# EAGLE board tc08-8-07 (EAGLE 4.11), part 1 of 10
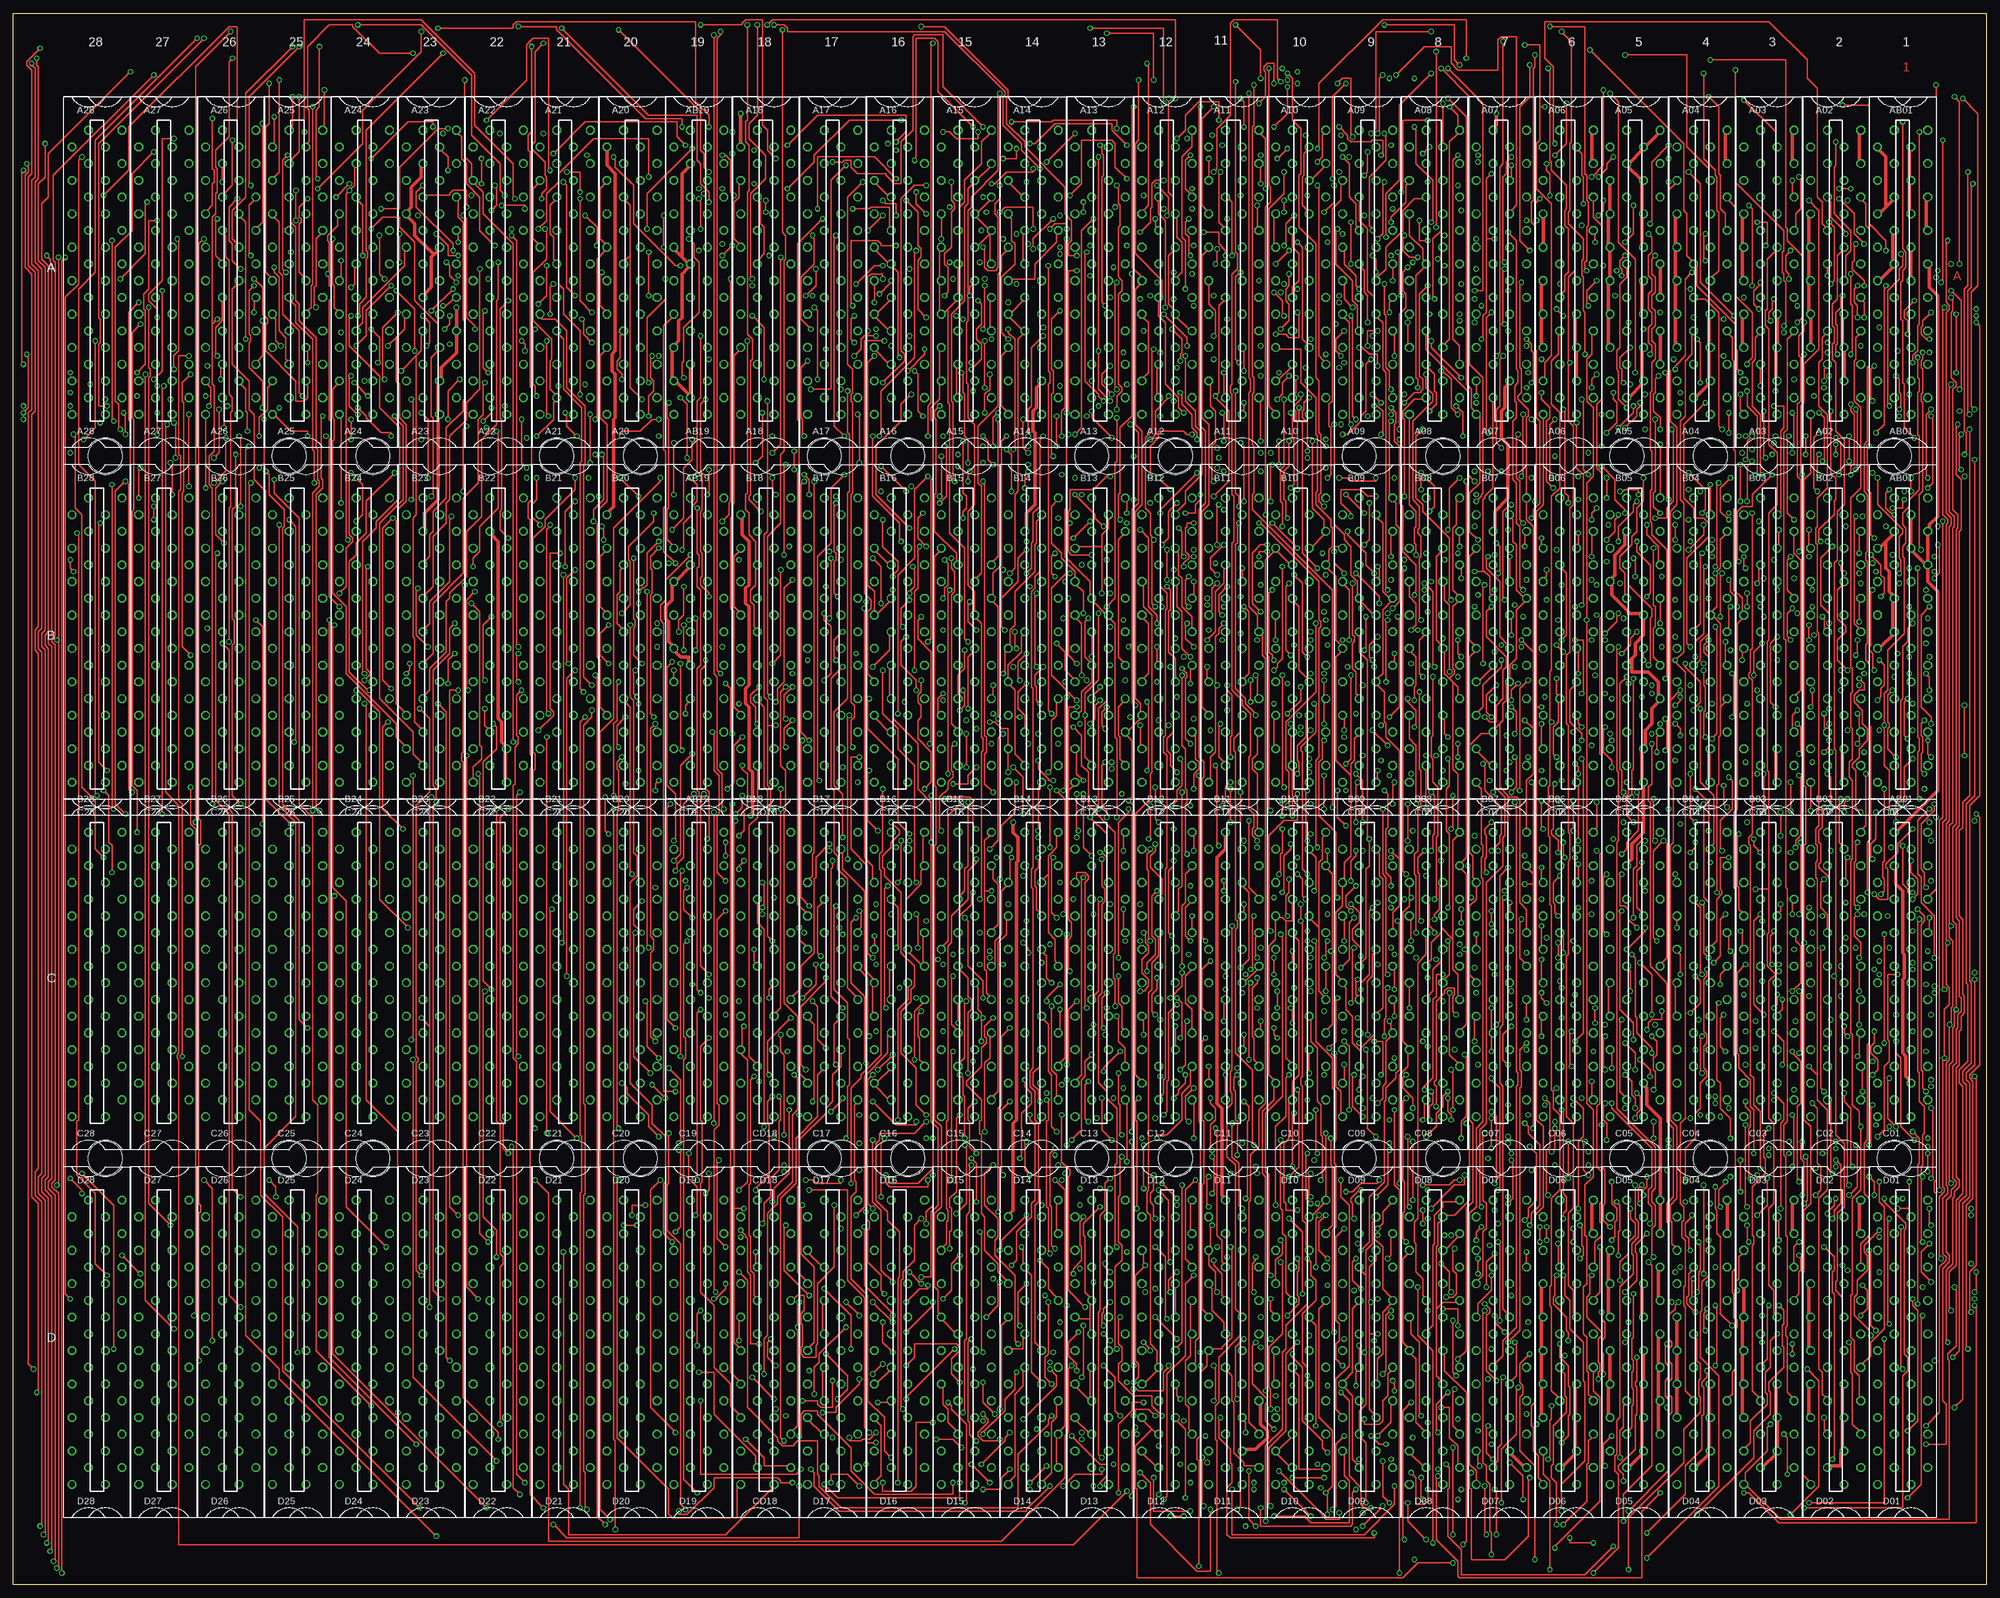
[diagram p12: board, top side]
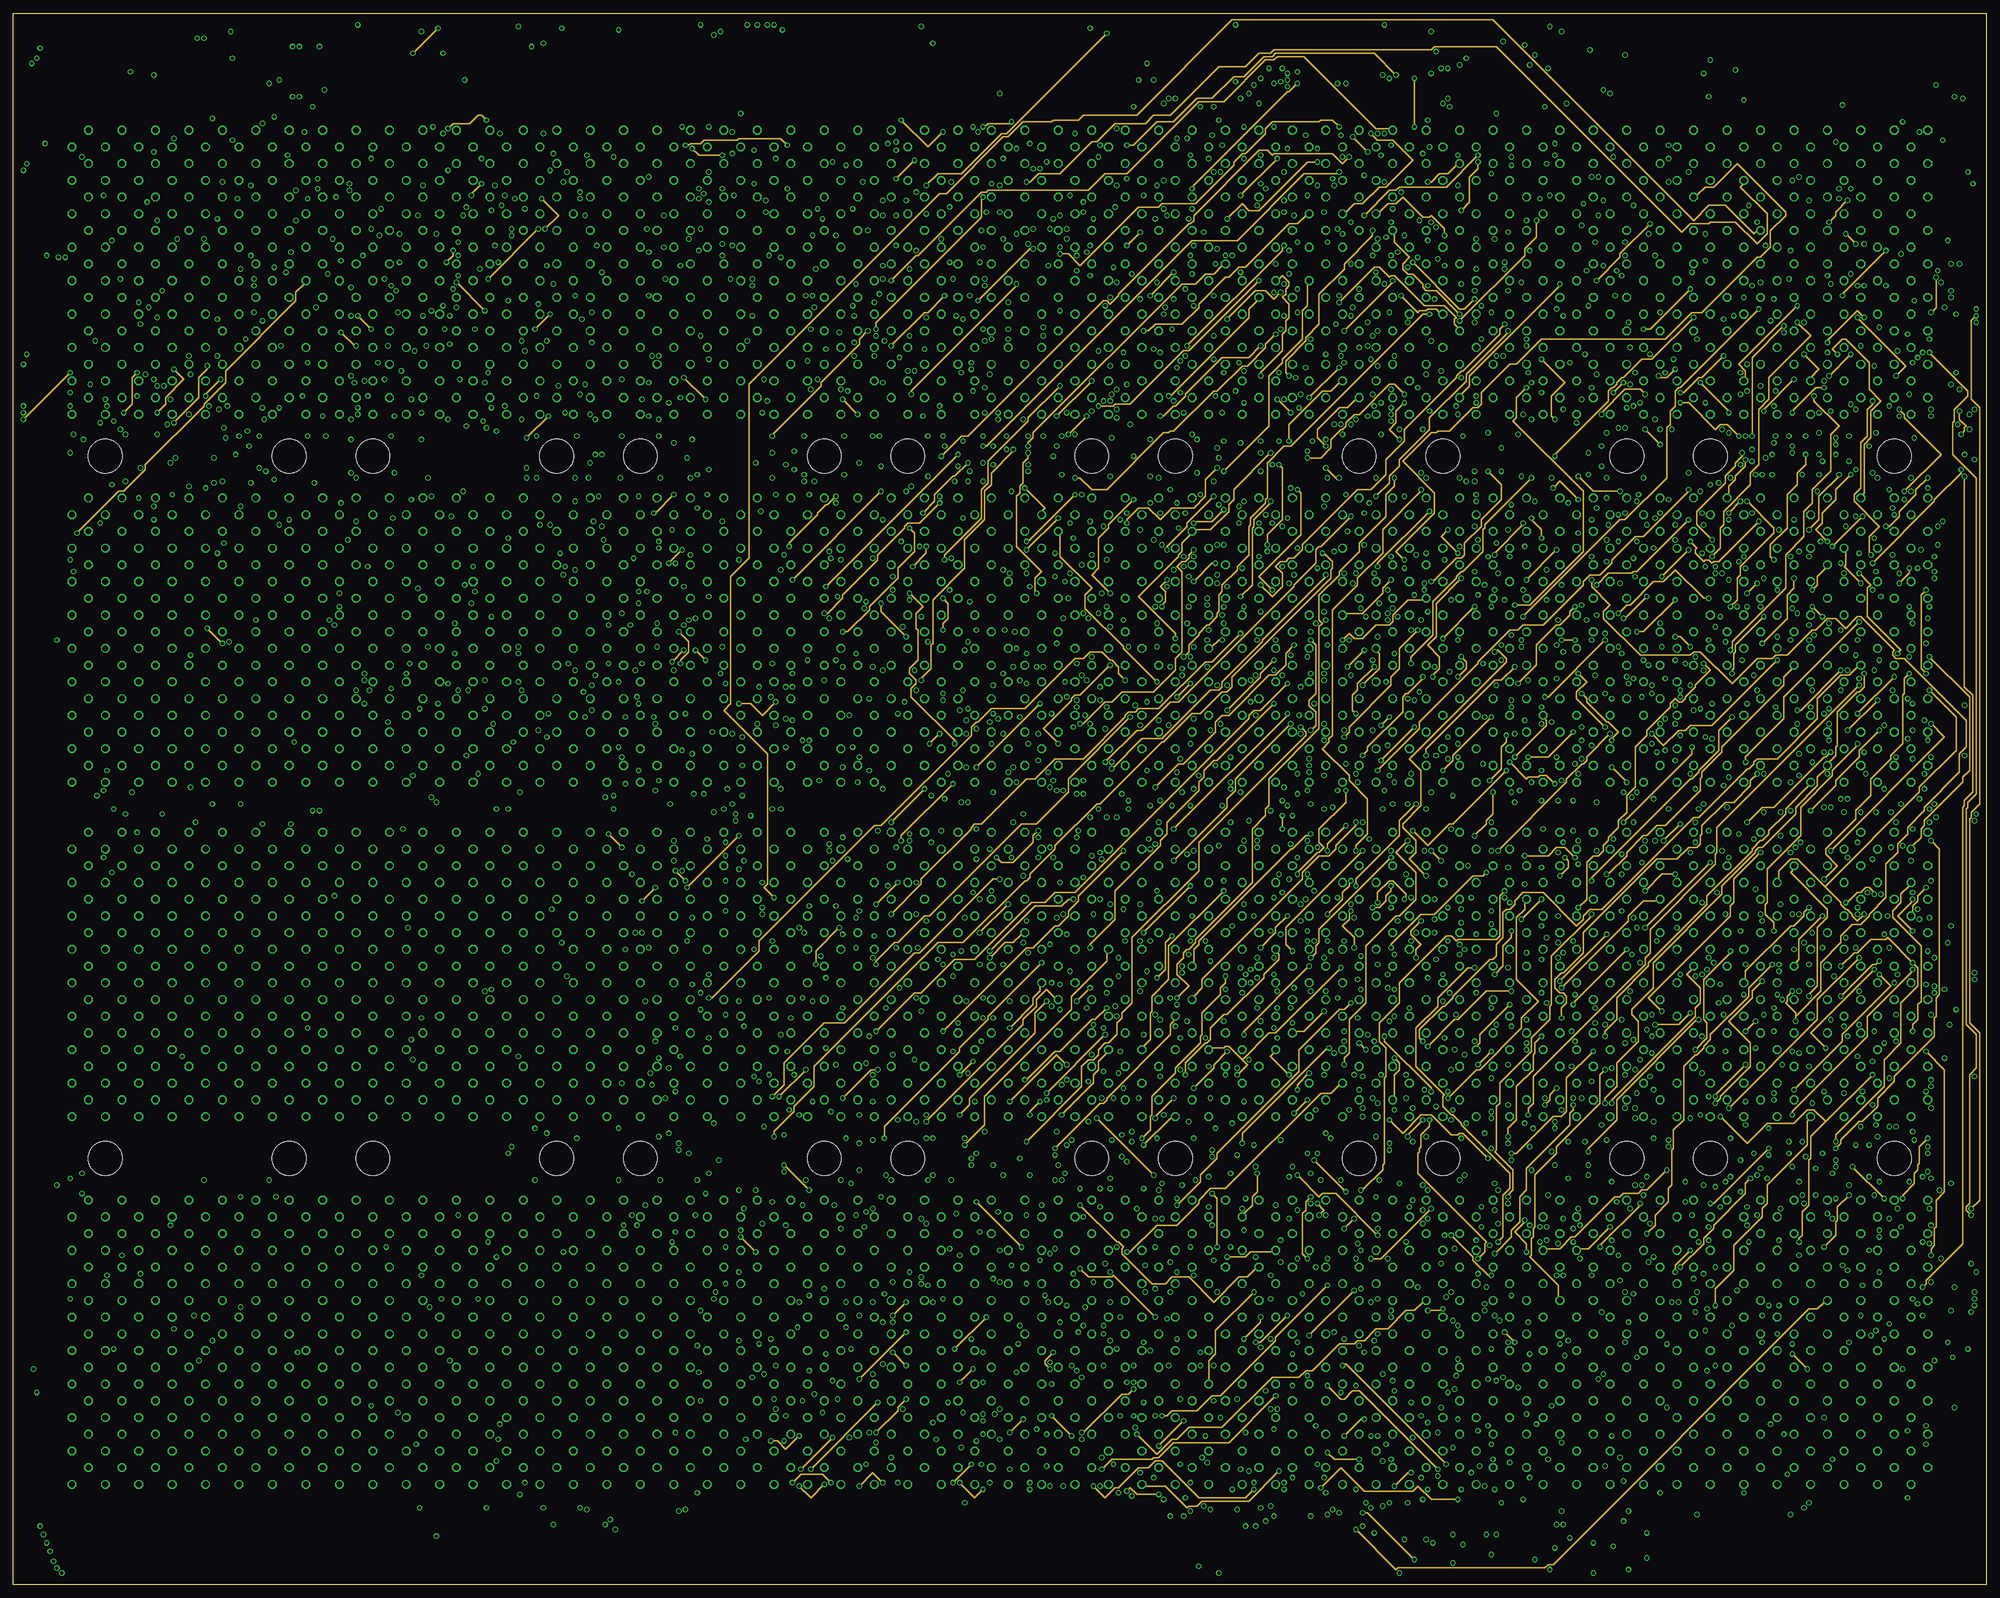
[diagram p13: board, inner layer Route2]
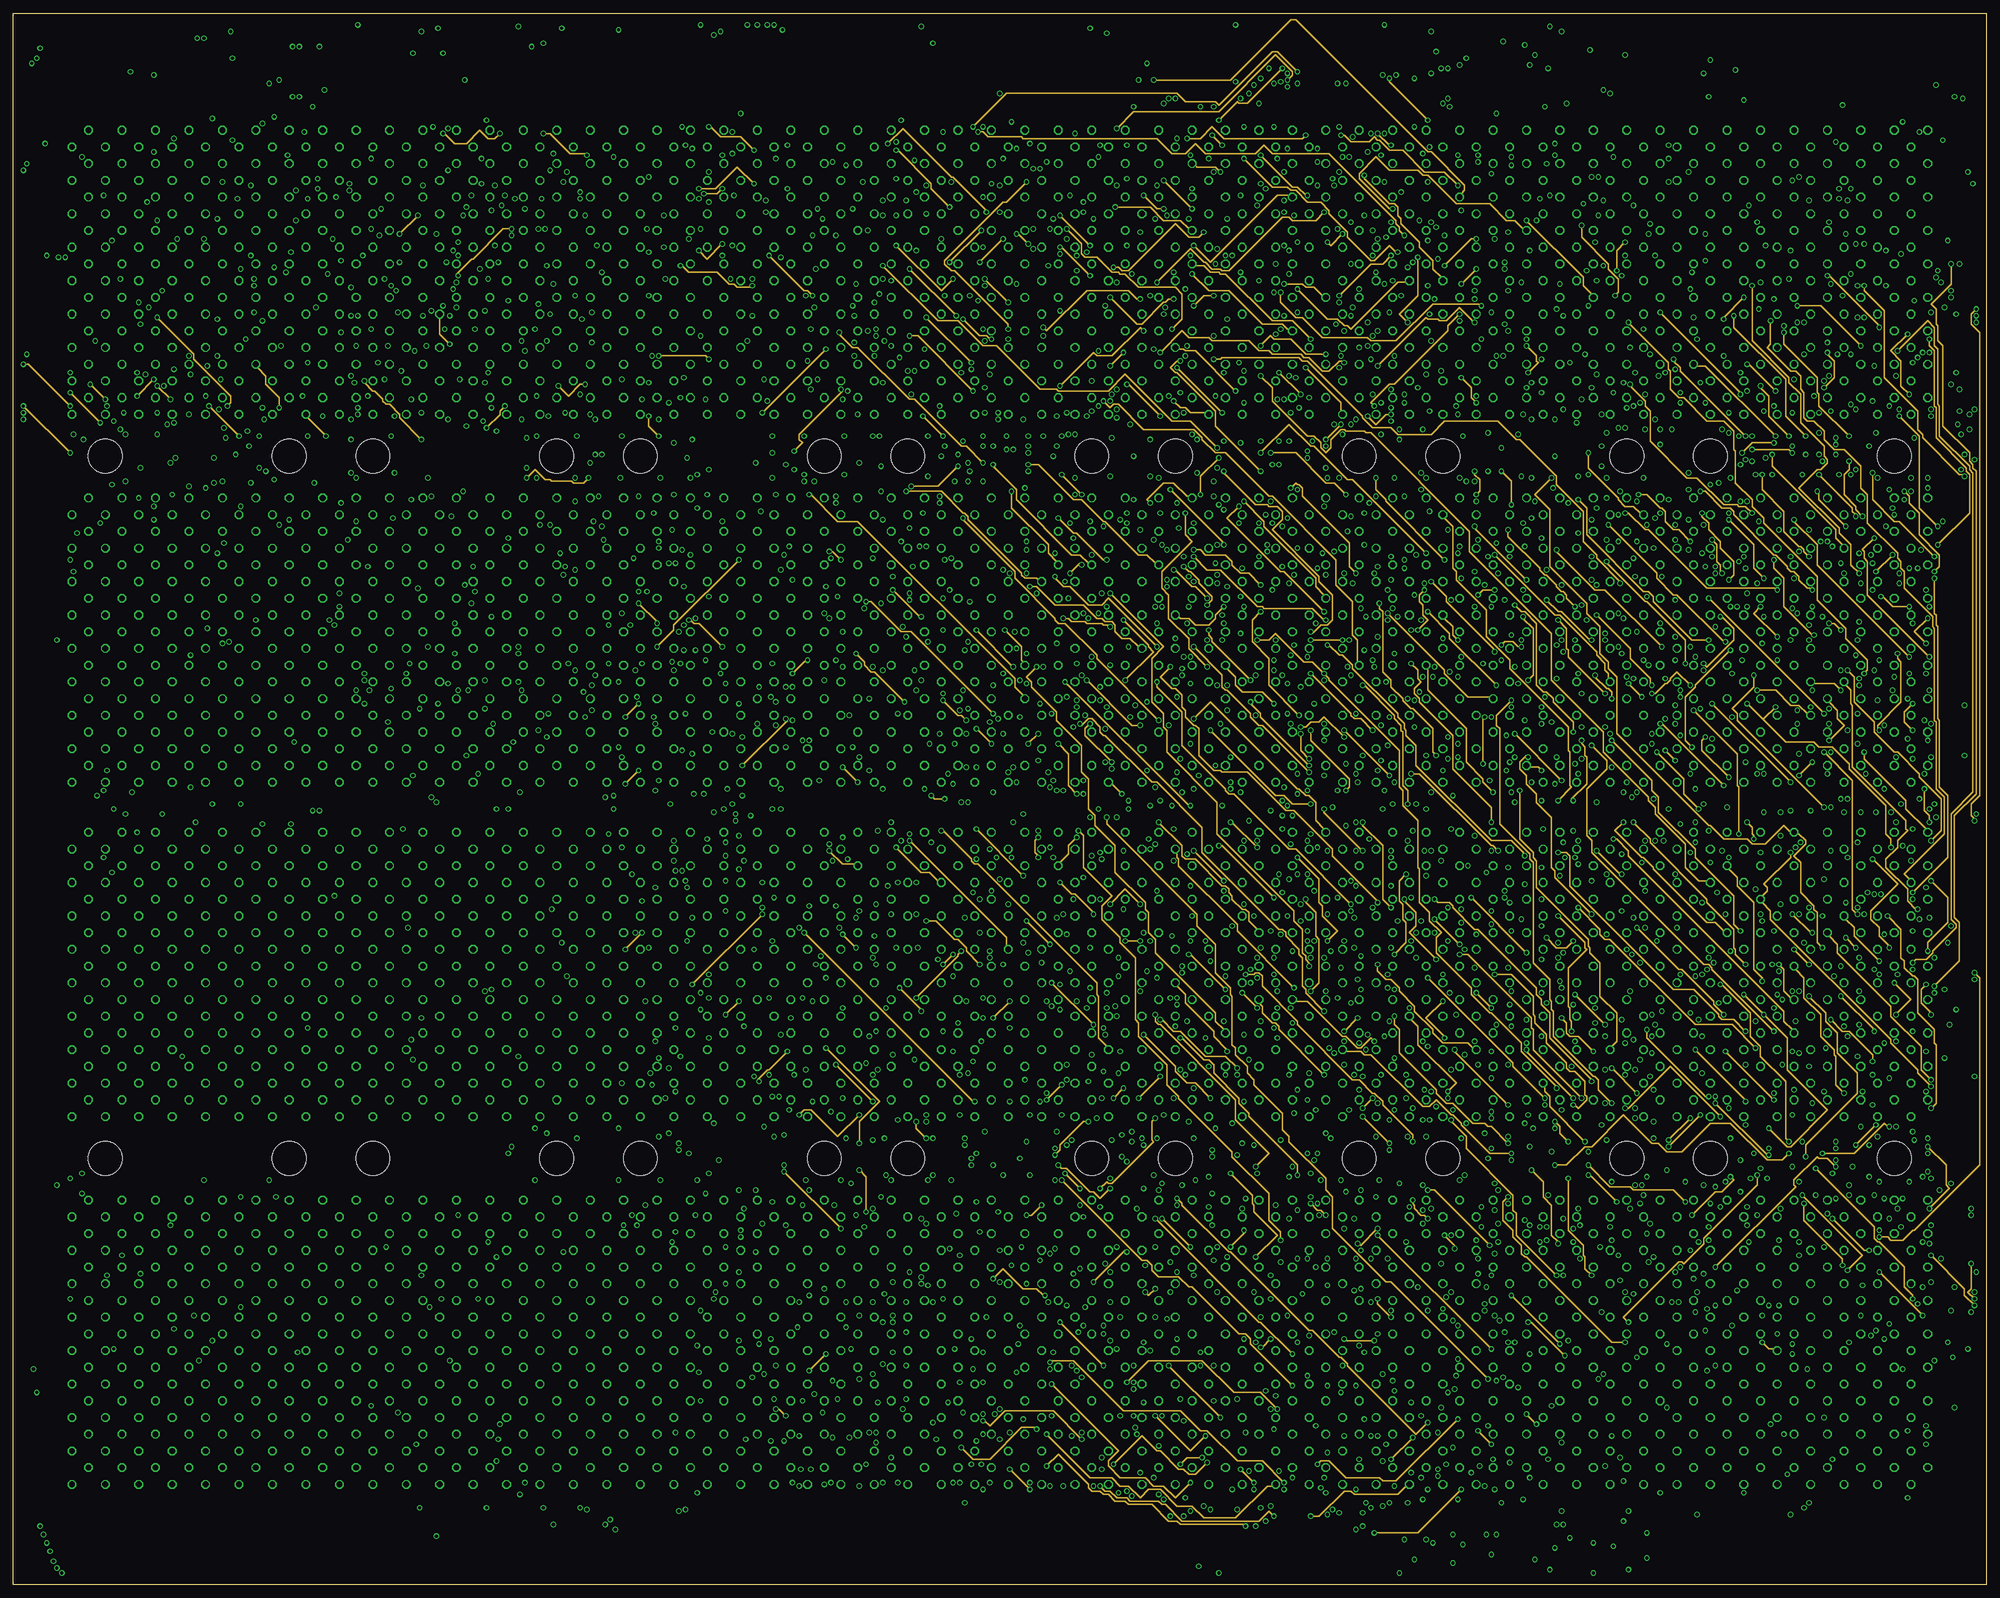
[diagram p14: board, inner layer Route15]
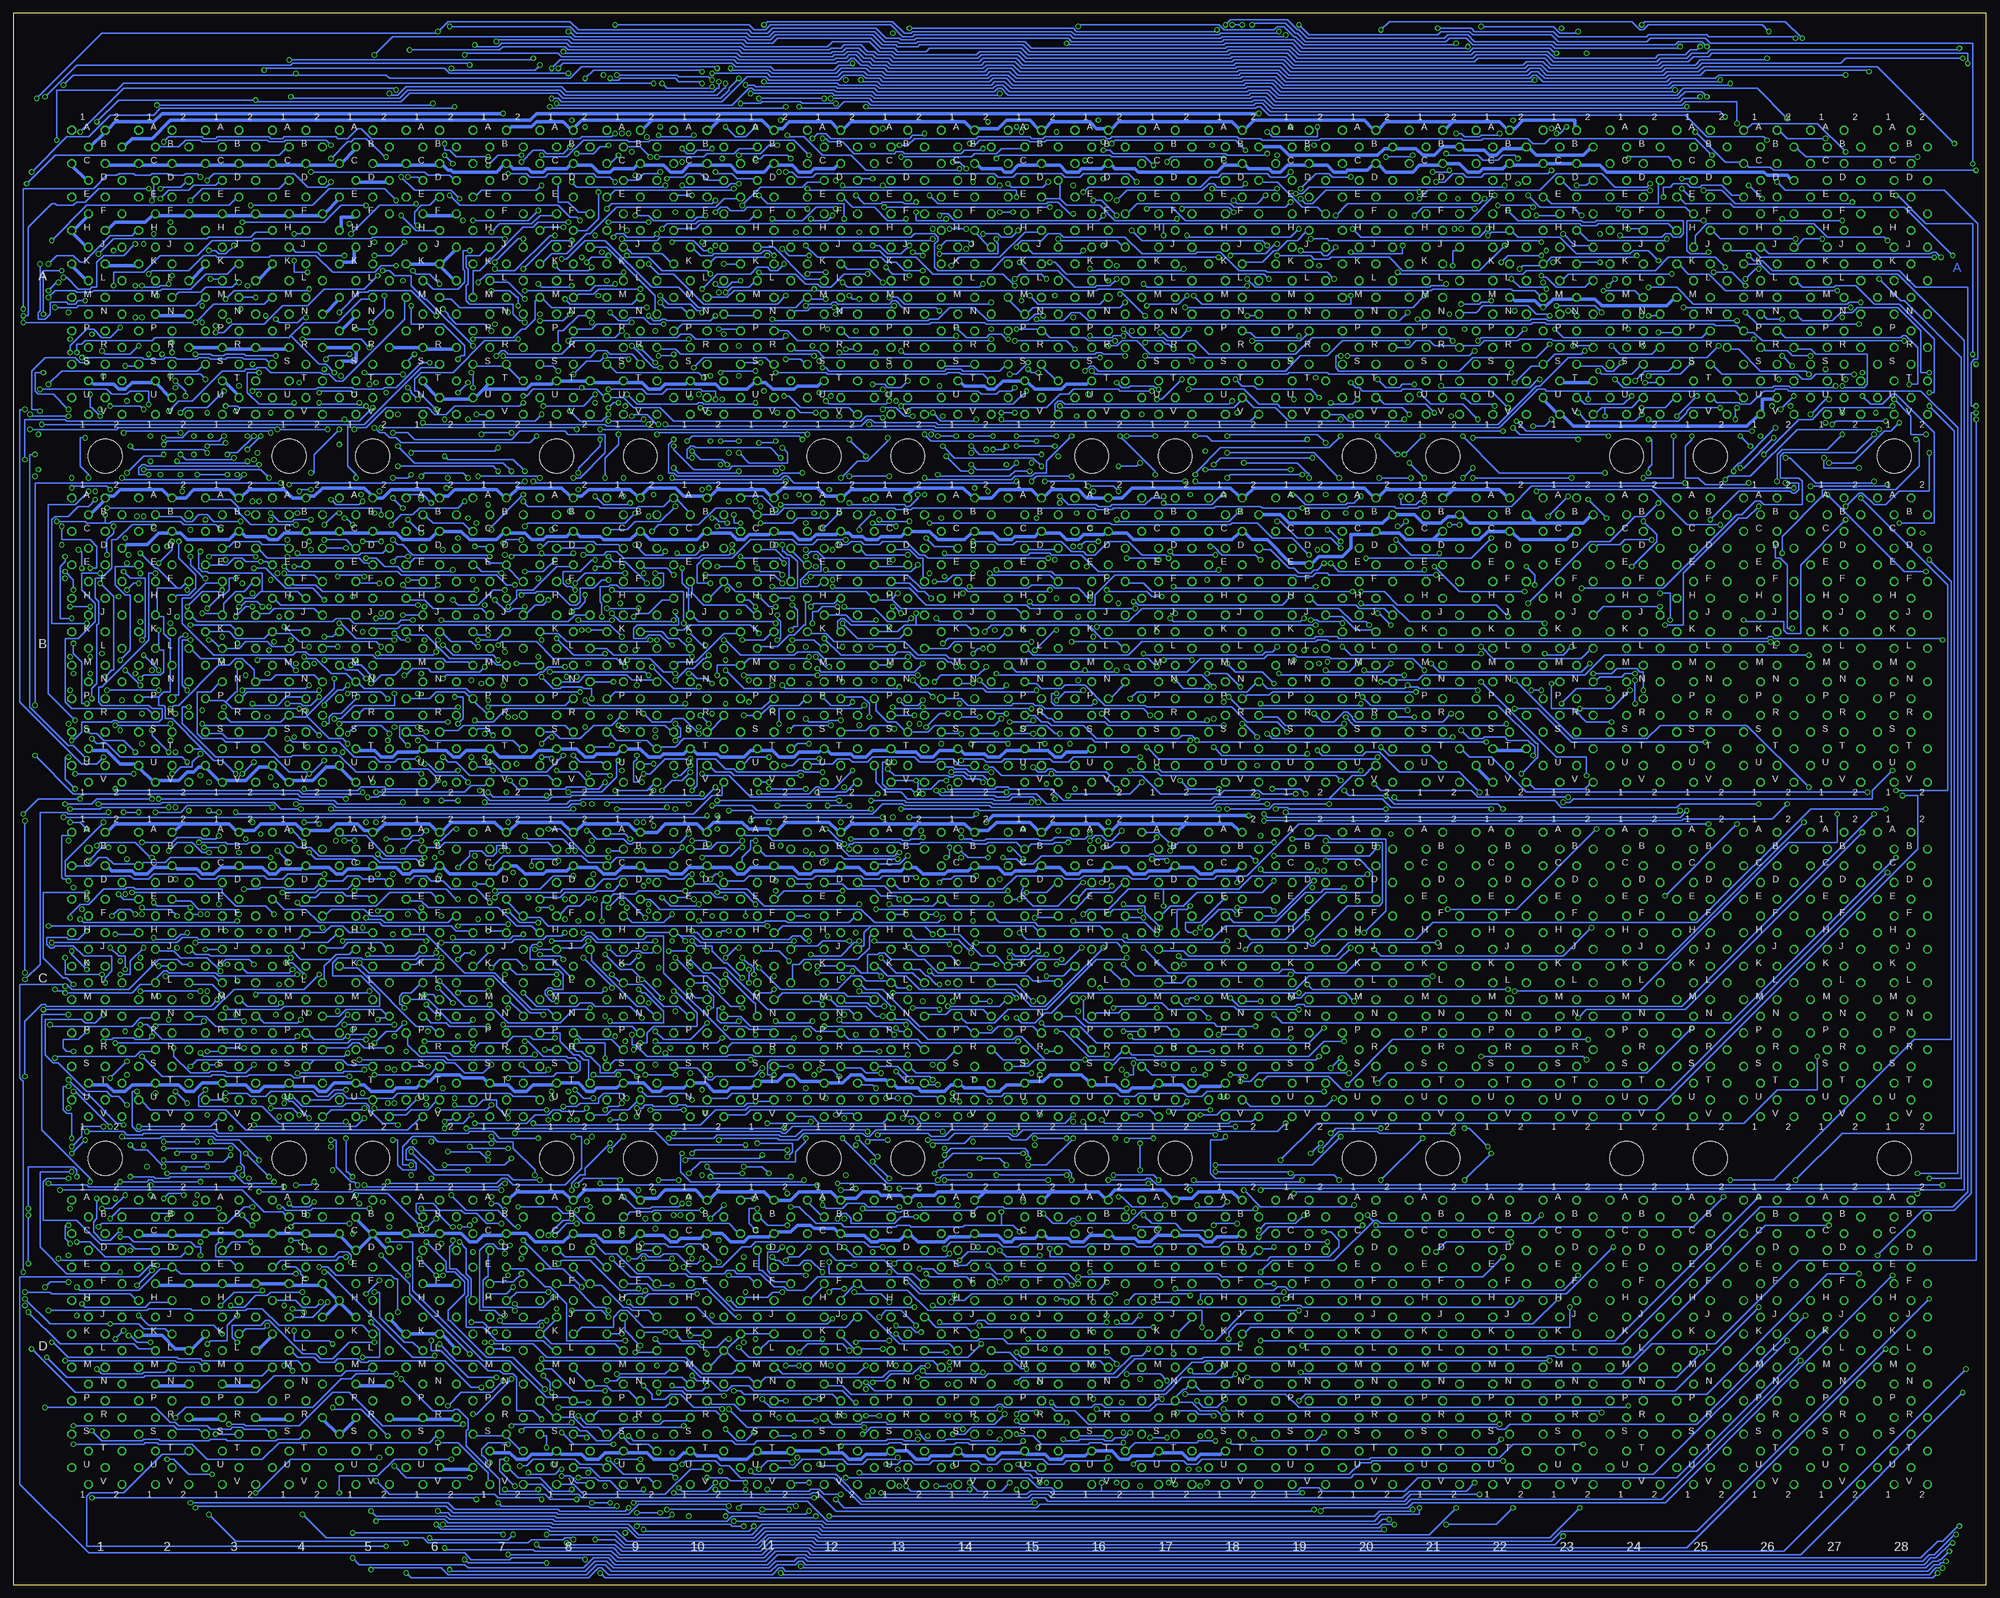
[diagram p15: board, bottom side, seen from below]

Size 374.71 x 298.44 mm. Coordinates in mm from the lower left corner, seen from the top.
Outline: 374.68,0 0,0 0.03,298.42 374.71,298.44 374.68,0
Copper layers (1*2*15*16): Top 0.035mm / dielectric 1.5mm / Route2 0.035mm / dielectric 0.15mm / Route15 0.035mm / dielectric 0.2mm / Bottom 0.035mm
Design rules "10mils": minimum track width 10mil, minimum drill 24mil, track to track 10mil, track to pad 10mil, pad to pad 10mil, via to via 10mil, smd to smd 10mil, copper to edge 40mil, drill to drill 10mil, minimum pad ring 10mil, minimum via ring 8mil, stop-mask expansion 0mil, vias tented up to drill 0mil, thermal gap 10mil
Net classes: 1 Power: width 0.635 mm, drill 0.381 mm, clearance 0.381 mm

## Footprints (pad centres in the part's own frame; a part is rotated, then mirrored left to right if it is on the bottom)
H807 = drill 1.092 octagon: A1 4.763,28.575; A2 -1.587,28.575; B1 1.587,25.4; B2 -4.763,25.4; C1 4.763,22.225; C2 -1.587,22.225; D1 1.587,19.05; D2 -4.763,19.05; E1 4.763,15.875; E2 -1.587,15.875; F1 1.587,12.7; F2 -4.763,12.7; H1 4.763,9.525; H2 -1.587,9.525; J1 1.587,6.35; J2 -4.763,6.35; K1 4.763,3.175; K2 -1.587,3.175; L1 1.587,0; L2 -4.763,0; M1 4.763,-3.175; M2 -1.587,-3.175; N1 1.587,-6.35; N2 -4.763,-6.35; P1 4.763,-9.525; P2 -1.587,-9.525; R1 1.587,-12.7; R2 -4.763,-12.7; S1 4.763,-15.875; S2 -1.587,-15.875; T1 1.587,-19.05; T2 -4.763,-19.05; U1 4.763,-22.225; U2 -1.587,-22.225; V1 1.587,-25.4; V2 -4.763,-25.4
H807-2 = drill 1.092 octagon: AA1 4.763,60.325; AA2 -1.587,60.325; AB1 1.587,57.15; AB2 -4.763,57.15; AC1 4.763,53.975; AC2 -1.587,53.975; AD1 1.587,50.8; AD2 -4.763,50.8; AE1 4.763,47.625; AE2 -1.587,47.625; AF1 1.587,44.45; AF2 -4.763,44.45; AH1 4.763,41.275; AH2 -1.587,41.275; AJ1 1.587,38.1; AJ2 -4.763,38.1; AK1 4.763,34.925; AK2 -1.587,34.925; AL1 1.587,31.75; AL2 -4.763,31.75; AM1 4.763,28.575; AM2 -1.587,28.575; AN1 1.587,25.4; AN2 -4.763,25.4; AP1 4.763,22.225; AP2 -1.587,22.225; AR1 1.587,19.05; AR2 -4.763,19.05; AS1 4.763,15.875; AS2 -1.587,15.875; AT1 1.587,12.7; AT2 -4.763,12.7; AU1 4.763,9.525; AU2 -1.587,9.525; AV1 1.587,6.35; AV2 -4.763,6.35; BA1 4.763,-9.525; BA2 -1.587,-9.525; BB1 1.587,-12.7; BB2 -4.763,-12.7; BC1 4.763,-15.875; BC2 -1.587,-15.875; BD1 1.587,-19.05; BD2 -4.763,-19.05; BE1 4.763,-22.225; BE2 -1.587,-22.225; BF1 1.587,-25.4; BF2 -4.763,-25.4; BH1 4.763,-28.575; BH2 -1.587,-28.575; BJ1 1.587,-31.75; BJ2 -4.763,-31.75; BK1 4.763,-34.925; BK2 -1.587,-34.925; BL1 1.587,-38.1; BL2 -4.763,-38.1; BM1 4.763,-41.275; BM2 -1.587,-41.275; BN1 1.587,-44.45; BN2 -4.763,-44.45; BP1 4.763,-47.625; BP2 -1.587,-47.625; BR1 1.587,-50.8; BR2 -4.763,-50.8; BS1 4.763,-53.975; BS2 -1.587,-53.975; BT1 1.587,-57.15; BT2 -4.763,-57.15; BU1 4.763,-60.325; BU2 -1.587,-60.325; BV1 1.587,-63.5; BV2 -4.763,-63.5
CBLOCK = hole 6.452: 7.938,68.263; 42.862,68.263

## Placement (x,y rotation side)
A02  M903  [H807]  346.11,247.64 0 top
A03  M903  [H807]  333.41,247.64 0 top
A04  M903  [H807]  320.71,247.64 0 top
A05  M903  [H807]  308.01,247.64 0 top
A06  M903  [H807]  295.31,247.64 0 top
A07  M161  [H807]  282.61,247.64 0 top
A08  M206  [H807]  269.91,247.64 0 top
A09  M117  [H807]  257.21,247.64 0 top
A10  M113  [H807]  244.51,247.64 0 top
A11  M111  [H807]  231.81,247.64 0 top
A12  M113  [H807]  219.11,247.64 0 top
A13  H807  [H807]  206.41,247.64 0 top
A14  M302  [H807]  193.71,247.64 0 top
A15  M627  [H807]  181.01,247.64 0 top
A16  M602  [H807]  168.31,247.64 0 top
A17  H807  [H807]  155.61,247.64 0 top
A18  G888  [H807]  142.91,247.64 0 top
A20  G888  [H807]  117.51,247.64 0 top
A21  G888  [H807]  104.81,247.64 0 top
A22  M502  [H807]  92.11,247.64 0 top
A23  M633  [H807]  79.41,247.64 0 top
A24  W023  [H807]  66.71,247.64 0 top
A25  [H807]  54.01,247.64 0 top
A26  [H807]  41.31,247.64 0 top
A27  H807  [H807]  28.61,247.64 0 top
A28  H807  [H807]  15.91,247.64 0 top
AB01  G821  [H807-2]  358.81,215.89 0 top
AB19  W032  [H807-2]  130.21,215.89 0 top
B02  M623  [H807]  346.11,177.79 0 top
B03  M623  [H807]  333.41,177.79 0 top
B04  M623  [H807]  320.71,177.79 0 top
B05  M623  [H807]  308.01,177.79 0 top
B06  M111  [H807]  295.31,177.79 0 top
B07  M207  [H807]  282.61,177.79 0 top
B08  M113  [H807]  269.91,177.79 0 top
B09  M206  [H807]  257.21,177.79 0 top
B10  M627  [H807]  244.51,177.79 0 top
B11  M115  [H807]  231.81,177.79 0 top
B12  M117  [H807]  219.11,177.79 0 top
B13  M206  [H807]  206.41,177.79 0 top
B14  M206  [H807]  193.71,177.79 0 top
B15  M113  [H807]  181.01,177.79 0 top
B16  M602  [H807]  168.31,177.79 0 top
B17  H807  [H807]  155.61,177.79 0 top
B18  G888  [H807]  142.91,177.79 0 top
B20  G888  [H807]  117.51,177.79 0 top
B21  G879  [H807]  104.81,177.79 0 top
B22  M633  [H807]  92.11,177.79 0 top
B23  W005  [H807]  79.41,177.79 0 top
B24  H807  [H807]  66.71,177.79 0 top
B25  H807  [H807]  54.01,177.79 0 top
B26  H807  [H807]  41.31,177.79 0 top
B27  H807  [H807]  28.61,177.79 0 top
B28  H807  [H807]  15.91,177.79 0 top
C01  M101  [H807]  358.81,114.29 0 top
C02  M101  [H807]  346.11,114.29 0 top
C03  M101  [H807]  333.41,114.29 0 top
C04  M103  [H807]  320.71,114.29 0 top
C05  M103  [H807]  308.01,114.29 0 top
C06  M111  [H807]  295.31,114.29 0 top
C07  M207  [H807]  282.61,114.29 0 top
C08  M121  [H807]  269.91,114.29 0 top
C09  M206  [H807]  257.21,114.29 0 top
C10  M121  [H807]  244.51,114.29 0 top
C11  M113  [H807]  231.81,114.29 0 top
C12  M115  [H807]  219.11,114.29 0 top
C13  M111  [H807]  206.41,114.29 0 top
C14  M206  [H807]  193.71,114.29 0 top
C15  M113  [H807]  181.01,114.29 0 top
C16  M627  [H807]  168.31,114.29 0 top
C17  M111  [H807]  155.61,114.29 0 top
C19  H807  [H807]  130.21,114.29 0 top
C20  H807  [H807]  117.51,114.29 0 top
C21  H807  [H807]  104.81,114.29 0 top
C22  H807  [H807]  92.11,114.29 0 top
C23  H807  [H807]  79.41,114.29 0 top
C24  H807  [H807]  66.71,114.29 0 top
C25  H807  [H807]  54.01,114.29 0 top
C26  H807  [H807]  41.31,114.29 0 top
C27  H807  [H807]  28.61,114.29 0 top
C28  H807  [H807]  15.91,114.29 0 top
CD18  M228  [H807-2]  142.91,82.54 0 top
D01  H807  [H807]  358.81,44.44 0 top
D02  M903  [H807]  346.11,44.44 0 top
D03  M903  [H807]  333.41,44.44 0 top
D04  M903  [H807]  320.71,44.44 0 top
D05  M903  [H807]  308.01,44.44 0 top
D06  M903  [H807]  295.31,44.44 0 top
D07  M161  [H807]  282.61,44.44 0 top
D08  M207  [H807]  269.91,44.44 0 top
D09  M121  [H807]  257.21,44.44 0 top
D10  M119  [H807]  244.51,44.44 0 top
D11  M206  [H807]  231.81,44.44 0 top
D12  M627  [H807]  219.11,44.44 0 top
D13  M602  [H807]  206.41,44.44 0 top
D14  M307  [H807]  193.71,44.44 0 top
D15  M401  [H807]  181.01,44.44 0 top
D16  M302  [H807]  168.31,44.44 0 top
D17  M602  [H807]  155.61,44.44 0 top
D19  H807  [H807]  130.21,44.44 0 top
D20  H807  [H807]  117.51,44.44 0 top
D21  H807  [H807]  104.81,44.44 0 top
D22  H807  [H807]  92.11,44.44 0 top
D23  H807  [H807]  79.41,44.44 0 top
D24  H807  [H807]  66.71,44.44 0 top
D25  H807  [H807]  54.01,44.44 0 top
D26  H807  [H807]  41.31,44.44 0 top
D27  H807  [H807]  28.61,44.44 0 top
D28  H807  [H807]  15.91,44.44 0 top
U$17  [CBLOCK]  9.56,12.69 0 top
U$18  [CBLOCK]  60.36,12.69 0 top
U$19  [CBLOCK]  111.16,12.69 0 top
U$20  [CBLOCK]  161.96,12.69 0 top
U$66  [CBLOCK]  212.76,12.69 0 top
U$67  [CBLOCK]  263.56,12.69 0 top
U$68  [CBLOCK]  314.36,12.69 0 top
U$69  [CBLOCK]  314.36,146.04 0 top
U$70  [CBLOCK]  263.56,146.04 0 top
U$71  [CBLOCK]  212.76,146.04 0 top
U$72  [CBLOCK]  161.96,146.04 0 top
U$73  [CBLOCK]  111.16,146.04 0 top
U$74  [CBLOCK]  60.36,146.04 0 top
U$75  [CBLOCK]  9.56,146.04 0 top

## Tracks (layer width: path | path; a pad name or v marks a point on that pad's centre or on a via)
00\  (via drill 0.61)
  Top 0.254: v89.57,166.36 89.57,163.18 90.21,162.55 B22.S2 | v53.38,160.01 53.69,160.33 53.69,200.96 v52.42,202.24 | v38.14,209.22 40.36,211.44 v40.36,217.79 | v46.71,212.08 47.66,213.03 v47.66,221.29 | v47.34,223.51 47.34,228.59 44.8,231.13 44.8,235.89 45.12,236.21 45.12,237.16 44.8,237.48 44.8,245.73 v45.76,246.68 | v51.79,249.23 51.15,249.86 51.15,270.5 v52.11,271.45 | v206.41,273.36 206.73,273.04 206.73,271.77 207.05,271.45 207.05,267.64 206.73,267.32 206.73,243.51 v207.36,242.87 | v218.48,241.29 222.92,236.84 v222.92,235.26 | v241.34,254.3 241.65,254.62 241.65,258.43 v243.24,260.02 | v284.52,269.55 284.52,267.32 A07.D1
  Route2 0.254: v222.92,235.26 241.02,253.35 241.02,253.99 v241.34,254.3 | v256.58,260.02 261.34,264.78 262.61,264.78 263.24,265.42 272.13,265.42 v278.17,271.45
  Bottom 0.254: v89.57,166.36 85.13,166.36 78.78,160.01 v53.38,160.01 | v52.42,202.24 47.03,207.63 37.18,207.63 36.87,207.31 36.23,207.31 35.6,207.95 35.6,209.22 v38.14,209.22 | v40.36,217.79 46.07,212.08 v46.71,212.08 | v47.66,221.29 47.66,223.51 v47.34,223.51 | v45.76,246.68 48.3,249.23 v51.79,249.23 | v52.11,271.45 55.28,274.62 82.9,274.62 83.86,273.67 86.08,273.67 87.03,274.62 95.6,274.62 95.92,274.31 99.41,274.31 99.73,274.62 126.4,274.62 126.72,274.31 137.51,274.31 137.83,274.62 141.96,274.62 142.28,274.94 166.09,274.94 166.41,274.62 167.04,274.62 167.36,274.94 178.79,274.94 179.11,274.62 181.33,274.62 181.65,274.94 191.49,274.94 191.81,274.62 203.55,274.62 204.82,273.36 v206.41,273.36 | v207.36,242.87 207.68,242.56 217.21,242.56 v218.48,241.29 | v243.24,260.02 243.56,259.7 244.83,259.7 245.46,259.07 253.08,259.07 254.04,260.02 v256.58,260.02 | v278.17,271.45 282.61,271.45 v284.52,269.55
0_TO_AC\  (via drill 0.61)
  Top 0.254: v290.23,163.5 290.23,159.37 B06.T2 | v312.77,182.55 B05.H1
  Route2 0.254: v290.87,168.58 291.5,168.58 v302.3,179.37
  Bottom 0.254: v290.23,163.5 289.28,164.45 289.28,168.58 v290.87,168.58 | v302.3,179.37 302.61,179.69 309.6,179.69 312.46,182.55 v312.77,182.55
0_TO_DTB  (via drill 0.61)
  Top 0.254: v233.72,104.44 233.72,102.22 C11.R1 | v212.76,206.05 v212.76,214.3 | v215.94,217.48 216.89,218.43 216.89,222.87 219.43,225.41 v219.43,225.73
  Route2 0.254: v233.72,104.44 233.72,105.08 v246.1,117.46 | v208.32,188.27 204.82,191.76 206.09,193.03 206.09,198.74 208,200.65 208,201.28 v212.76,206.05 | v219.43,225.73 219.75,225.73 234.67,240.65 234.67,242.24 236.26,243.83 A11.M1
  Route15 0.254: v246.1,117.46 246.1,118.1 245.46,118.73 245.46,119.37 244.83,120 244.83,124.45 243.24,126.03 243.24,127.94 228.64,142.55 228.64,148.58 219.11,158.1 219.11,162.23 218.48,162.86 218.48,165.4 216.25,167.63 216.25,175.88 218.48,178.11 v208.32,188.27
  Bottom 0.254: v212.76,214.3 v215.94,217.48
0_TO_DTB\  (via drill 0.61)
  Top 0.254: C09.K2 255.94,118.1 256.89,119.05 256.89,135.88 257.53,136.51 v257.53,141.59 257.21,141.91 257.21,175.56 255.62,177.15 B09.K2 255.94,181.6 v255.94,185.41 | v261.97,185.41 263.24,186.68 263.24,200.65 262.61,201.28 262.61,205.41 262.29,205.73 B09.A1 261.34,206.68 261.34,220.65 v261.66,220.97 | v239.43,245.42 241.02,243.83 241.02,241.29 v241.34,240.97 | v254.04,240.97 254.35,240.65 254.35,221.92 v254.99,221.29
  Bottom 0.254: v257.53,141.59 258.48,142.55 261.34,142.55 C09.A1 | B10.L1 246.73,178.11 248.32,179.69 250.23,179.69 251.5,180.96 B09.K2 | v255.94,185.41 v261.97,185.41 | v239.43,245.42 239.11,245.42 238.16,246.37 234.99,246.37 234.03,247.32 A11.L1 | v241.34,240.97 242.29,240.02 250.54,240.02 250.86,240.33 251.5,240.33 251.81,240.02 253.08,240.02 v254.04,240.97 | v254.99,221.29 255.31,220.97 v261.66,220.97
0_TO_EF  (via drill 0.61)
  Top 0.254: v231.49,252.4 231.49,262.56 230.86,263.19 A11.E2
  Bottom 0.254: v231.49,252.4 231.81,252.08 241.34,252.08 242.29,251.13 A10.K2
0_TO_EF\  (via drill 0.61)
  Top 0.254: v228,280.66 225.78,278.43 225.78,261.93 226.73,260.97 A11.F2 | v272.77,280.66 274.36,279.07 274.36,276.85 A08.A1 274.36,275.58 272.77,273.99 272.77,236.52 271.82,235.57 A08.R1
  Bottom 0.254: A08.R1 271.18,235.57 271.18,238.11 270.23,238.11 267.37,240.97 265.78,240.97 A08.N2 | v228,280.66 228.32,280.34 272.45,280.34 v272.77,280.66
0_TO_LPB\
  Top 0.254: D08.A1 274.04,72.69 271.5,72.69 271.5,71.74 269.91,70.16 269.91,64.76 269.59,64.44 269.59,49.2 268.64,48.25 D08.K2
  Bottom 0.254: D12.J2 214.98,50.47 216.57,48.88 254.99,48.88 258.16,52.06 259.43,52.06 260.7,50.79 260.7,48.88 266.74,48.88 267.69,47.93 D08.K2
0_TO_STA
  Bottom 0.254: A11.N1 234.03,240.97 239.11,240.97 A10.N2
0_TO_STA\  (via drill 0.61)
  Top 0.254: 288.64,162.55 v287.06,164.14 | 288.64,162.55 288.64,153.98 287.37,152.71 C07.A1 | 288.64,177.15 v286.42,179.37 | 288.64,177.15 288.64,162.55 | 288.64,177.15 288.64,200.96 287.37,202.24 B07.A1 287.37,221.6 287.69,221.92 287.69,223.19 285.79,225.09 285.79,225.73 286.42,226.36 286.42,230.81 286.1,231.13 286.1,247 v286.42,247.32 | v240.7,238.43 242.29,240.02 242.29,243.19 241.65,243.83 241.65,246.05 242.29,246.68 v242.29,248.91 | v258.16,252.4 258.8,251.77 v258.8,249.23
  Bottom 0.254: v287.06,164.14 286.74,163.82 283.56,163.82 281.02,166.36 232.45,166.36 230.86,167.95 B11.P2 | v286.42,179.37 282.93,179.37 281.66,180.64 B07.K2 | v240.7,238.43 237.21,238.43 A11.P1 | v242.29,248.91 242.92,249.54 251.5,249.54 254.04,252.08 257.85,252.08 v258.16,252.4 | v258.8,249.23 259.12,248.91 284.83,248.91 v286.42,247.32
0_TO_STATE\  (via drill 0.61)
  Top 0.254: v167.99,88.25 167.99,109.21 169.9,111.11 C16.L1
  Bottom 0.254: v167.99,88.25 167.36,87.62 143.86,87.62 143.55,87.94 139.42,87.94 138.78,88.57 CD18.AV2
0_TO_W\  (via drill 0.61)
  Top 0.254: v140.69,96.51 140.05,95.87 140.05,76.19 139.74,75.87 139.74,66.35 140.05,66.03 140.05,59.68 140.69,59.04 140.69,54.92 141.01,54.6 CD18.BH2 | v143.55,96.83 143.23,97.14 143.23,103.18 v147.67,107.62 | v165.77,109.52 165.45,109.84 165.45,132.07 v166.09,132.7
  Bottom 0.254: v140.69,96.51 141.01,96.83 v143.55,96.83 | v147.67,107.62 149.26,109.21 155.29,109.21 156.56,110.48 159.1,110.48 159.74,109.84 165.45,109.84 v165.77,109.52 | v166.09,132.7 166.72,132.07 170.85,132.07 172.44,130.48 C16.E1
01\  (via drill 0.61)
  Top 0.254: v176.88,244.78 177.52,245.42 177.52,250.18 176.88,250.81 176.88,252.72 178.15,253.99 178.15,260.66 178.79,261.29 178.79,262.24 178.15,262.88 v178.15,266.37 | v185.77,266.05 186.41,266.05 188.63,268.28 193.71,268.28 v193.71,268.91 | v201.65,275.58 v196.25,270.18
  Route2 0.254: v166.72,235.26 173.07,241.61 173.71,241.61 v176.88,244.78
  Route15 0.254: v82.9,235.57 81,237.48 A23.N1 | v122.59,233.35 131.48,233.35 v132.12,232.71 | v222.92,274.62 225.46,274.62 227.68,276.85 229.91,274.62 244.83,274.62 v245.46,275.26 | v252.13,275.26 252.77,275.26 254.04,273.99 257.53,273.99 258.48,274.94 259.12,274.31 259.43,274.31 261.34,272.4 263.88,272.4 268.01,268.28 271.82,268.28 v274.36,265.74
  Bottom 0.254: v82.9,235.57 85.44,233.03 97.51,233.03 100.05,230.49 122.91,230.49 123.54,231.13 123.54,233.35 v122.59,233.35 | v132.12,232.71 132.43,233.03 150.21,233.03 150.85,233.67 158.79,233.67 161.33,236.21 164.18,236.21 165.14,235.26 v166.72,235.26 | v178.15,266.37 179.11,265.42 185.14,265.42 v185.77,266.05 | v193.71,268.91 194.98,270.18 v196.25,270.18 | v201.65,275.58 201.97,275.26 203.87,275.26 204.51,274.62 219.43,274.62 220.38,275.58 221.97,275.58 v222.92,274.62 | v245.46,275.26 245.78,274.94 251.81,274.94 v252.13,275.26 | v274.36,265.74 275.31,264.78 285.79,264.78 286.74,263.83 A07.E1
1_TO_DF  (via drill 0.61)
  Top 0.254: v231.18,64.12 231.49,63.81 231.49,46.98 229.59,45.07 229.59,44.75 227.68,44.75 D11.L2 226.73,43.8 226.73,41.58 225.46,40.31 225.46,28.25 224.83,27.61 224.83,23.8 225.14,23.48 v225.14,3.48 | v233.4,71.43 232.76,72.06 232.76,80 231.49,81.27 v231.49,87.62 | v223.24,87.94 222.6,88.57 222.6,92.7 v224.19,94.28 | C12.J1 220.38,120 220.38,114.92 C12.L1 | v270.23,291.13 v270.23,257.8 | v22.26,287.32 6.7,271.77 6.7,263.51 5.43,262.24 5.43,251.77 6.7,250.49 6.7,180.96 6.07,180.33 6.07,178.42 6.7,177.79 6.7,77.46 6.07,76.82 6.07,74.92 7.34,73.65 7.34,6.66 v7.02,6.34
  Route2 0.254: v224.19,94.28 228,98.1 228,98.73 v230.54,101.27
  Route15 0.254: v231.18,64.12 234.03,66.98 v233.72,67.3 | v230.54,101.27 230.54,101.59 228,104.13 228,105.08 222.6,110.48 222.6,112.07 221.02,113.65 C12.L1
  Bottom 0.254: v233.72,67.3 234.99,68.57 234.99,71.43 v233.4,71.43 | v231.49,87.62 223.56,87.62 v223.24,87.94 | v270.23,257.8 273.72,257.8 274.04,257.48 A08.H1 | v270.23,291.13 269.91,290.82 237.21,290.82 236.57,290.18 219.11,290.18 218.79,290.5 216.89,290.5 216.25,291.13 214.35,291.13 213.08,289.86 211.81,289.86 211.17,289.23 208.63,289.23 208,288.6 190.85,288.6 190.22,289.23 184.5,289.23 183.23,287.96 142.59,287.96 142.28,288.28 134.02,288.28 132.43,286.69 87.03,286.69 86.4,287.32 85.13,287.32 83.86,286.05 61,286.05 60.36,286.69 54.33,286.69 53.38,287.64 22.58,287.64 v22.26,287.32 | v7.02,6.34 8.61,4.75 8.93,4.75 9.24,4.43 10.2,4.43 11.47,3.16 224.83,3.16 v225.14,3.48
1_TO_DTF  (via drill 0.61)
  Top 0.254: v216.89,32.06 215.62,33.32 213.08,33.32 213.08,32.37 v212.76,32.06 | v210.22,32.06 209.27,33.01 209.27,39.36 v207.05,41.58 | v167.04,49.83 v163.23,53.64 | v151.17,54.92 146.4,59.68 146.4,67.93 v146.72,68.25 | v142.28,68.57 142.59,68.88 142.59,72.38 143.86,73.65 143.86,77.14 145.45,78.73 145.45,87.94 145.77,88.25 145.77,92.38 v145.45,92.7 | v150.53,97.78 149.58,98.73 149.58,109.84 154.34,114.61 v154.34,115.24
  Route2 0.254: v145.45,92.7 v150.53,97.78 | v163.87,117.78 163.87,118.41 167.36,121.91 167.99,121.91 173.07,126.99 174.03,126.99 191.49,144.45 194.35,144.45 200.38,150.48 200.38,153.02 v212.13,164.77
  Route15 0.254: v226.41,28.25 223.56,25.39 v216.89,32.06 | v207.05,41.58 v198.79,49.83
  Bottom 0.254: v226.41,28.25 229.59,28.25 D11.S2 | v212.76,32.06 v210.22,32.06 | v198.79,49.83 198.47,49.52 192.12,49.52 191.49,50.15 190.22,50.15 189.58,49.52 167.36,49.52 v167.04,49.83 | v163.23,53.64 161.64,55.23 151.48,55.23 v151.17,54.92 | v146.72,68.25 146.4,68.57 v142.28,68.57 | v154.34,115.24 154.66,115.56 161.64,115.56 v163.87,117.78 | v212.13,164.77 212.13,167.31 213.4,168.58 216.89,168.58 B12.P2
02\  (via drill 0.61)
  Top 0.254: v77.82,265.74 76.55,264.47 76.55,261.61 83.54,254.62 v83.54,253.35 | v82.27,251.13 82.9,250.49 82.9,248.59 v84.17,247.32 | v89.57,241.92 89.25,241.61 89.25,231.13 v90.21,230.18 | v169.9,230.49 173.07,233.67 v173.07,234.62 | v184.5,227.32 v184.5,236.21 | v208.63,226.05 206.73,227.95 206.73,229.86 v208.32,231.45 | v255.62,234.94 256.26,234.94 257.53,233.67 259.12,233.67 v259.12,231.45
  Route2 0.254: v83.54,253.35 83.54,252.4 v82.27,251.13 | v89.57,241.92 v84.17,247.32
  Route15 0.254: v210.86,233.99 v208.32,231.45 | v217.84,233.99 221.97,238.11 223.24,236.84 227.05,236.84 227.68,236.21 234.67,236.21 236.57,234.3 238.48,234.3 239.11,233.67 244.51,233.67 245.15,233.03 246.1,233.03 248.64,230.49 249.91,230.49 251.81,232.4 252.45,232.4 v252.77,232.08 | v259.12,231.45 268.32,240.65 268.64,240.33 270.55,240.33 270.86,240.02 272.13,240.02 274.67,242.56 v277.53,239.7
  Bottom 0.254: v77.82,265.74 75.92,265.74 75.28,266.37 A23.D2 | v90.21,230.18 90.52,229.86 124.81,229.86 125.13,230.18 132.43,230.18 132.75,229.86 169.26,229.86 v169.9,230.49 | v173.07,234.62 174.66,236.21 v184.5,236.21 | v184.5,227.32 185.14,226.68 187.36,226.68 188,226.05 190.85,226.05 191.49,226.68 208,226.68 v208.63,226.05 | v210.86,233.99 211.17,233.67 217.52,233.67 v217.84,233.99 | v255.62,234.94 v252.77,232.08 | v277.53,239.7 277.85,240.02 278.48,240.02 279.75,241.29 279.75,243.19 288.01,243.19 288.64,243.83 288.64,246.68 288.33,247 288.33,249.86 288.64,250.18 288.64,252.4 286.1,252.4 284.83,253.67 A07.J1
03\  (via drill 0.61)
  Top 0.254: v86.08,261.61 86.08,264.78 83.54,264.78 82.9,264.15 82.9,263.83 78.46,263.83 A23.E2 | v92.75,261.93 97.19,261.93 v97.19,261.29 | v108.62,260.02 110.84,257.8 v110.84,254.3 | v120.69,244.78 v120.69,253.04 | v150.53,244.78 152.44,246.68 v152.44,249.86 | v283.88,245.73 283.88,241.92 A07.N1
  Route2 0.254: v230.54,240.33 235.94,245.73 237.84,245.73 239.43,244.14 v240.7,245.42
  Route15 0.254: v179.11,240.97 v170.22,249.86 | v240.7,245.42 240.7,243.51 243.56,240.65 244.83,240.65 248.64,236.84 257.21,236.84 257.85,236.21 262.61,236.21 269.59,243.19 278.48,243.19 v278.8,242.87
  Bottom 0.254: v86.08,261.61 86.4,261.93 v92.75,261.93 | v97.19,261.29 97.51,261.61 107.03,261.61 v108.62,260.02 | v110.84,254.3 110.84,252.72 120.37,252.72 v120.69,253.04 | v120.69,244.78 120.69,243.19 148.94,243.19 v150.53,244.78 | v152.44,249.86 152.75,249.54 169.9,249.54 v170.22,249.86 | v179.11,240.97 179.42,241.29 180.69,241.29 181.96,240.02 189.58,240.02 192.12,242.56 196.89,242.56 199.11,240.33 200.7,240.33 201.01,240.02 230.22,240.02 v230.54,240.33 | v278.8,242.87 278.8,244.46 279.12,244.46 280.39,245.73 v283.88,245.73
04\  (via drill 0.61)
  Top 0.254: v73.38,256.53 v73.38,251.13 | v88.94,270.81 v88.94,266.05 | v102.59,271.77 108.62,277.8 126.08,277.8 126.08,274.94 v127.67,273.36 | v147.04,273.36 152.75,279.07 169.58,279.07 169.58,275.9 v167.68,273.99 | v193.08,273.67 194.03,273.67 197.84,277.48 208.63,277.48 208.63,276.21 v211.49,273.36 | v262.61,286.69 268.01,292.09 273.09,292.09 273.09,288.91 274.36,287.64 281.98,287.64 281.98,293.36 282.61,293.99 285.47,293.99 285.47,261.93 284.52,260.97 A07.F1
  Route2 0.254: v87.03,263.83 87.03,264.15 v88.94,266.05 | v127.67,273.36 128.31,273.36 128.62,273.67 130.53,273.67 131.16,274.31 137.51,274.31 137.83,274.62 145.77,274.62 v147.04,273.36 | v211.49,273.36 212.76,273.36 217.21,277.8 220.38,277.8 224.83,282.24 227.68,282.24 231.81,286.37 233.72,286.37 237.53,290.18 239.11,290.18 239.75,290.82 258.48,290.82 v262.61,286.69
  Route15 0.254: v76.87,260.02 v73.38,256.53
  Bottom 0.254: v73.38,251.13 77.19,251.13 A23.K2 | v76.87,260.02 78.46,261.61 84.81,261.61 v87.03,263.83 | v88.94,270.81 89.57,271.45 91.79,271.45 92.75,270.5 95.6,270.5 96.56,271.45 102.27,271.45 v102.59,271.77 | v167.68,273.99 167.99,274.31 178.47,274.31 178.79,273.99 181.65,273.99 181.96,274.31 191.17,274.31 191.81,273.67 v193.08,273.67
05\  (via drill 0.61)
  Top 0.254: v269.28,258.75 269.59,259.07 269.59,266.69 266.42,269.86 266.42,276.53 v266.1,276.85 | v182.28,276.85 175.61,283.51 175.61,293.04 174.98,293.68 171.49,293.68 171.49,270.81 v171.17,270.5 | v167.68,267 163.55,271.13 152.75,271.13 v152.75,261.29 | v142.91,260.66 v142.91,262.88 | v136.88,263.83 136.24,264.47 136.24,270.5 135.29,271.45 v134.66,271.45 | v128.94,272.72 120.37,264.15 v120.37,257.48
  Route2 0.254: v266.1,286.05 v266.1,276.85 | v171.17,270.5 v167.68,267 | v134.66,271.45 130.21,271.45 v128.94,272.72
  Route15 0.254: v243.88,287.32 240.07,291.13 239.11,291.13 228.95,280.98 228.32,281.61 222.6,281.61 221.02,283.2 188.63,283.2 v182.28,276.85 | v94.65,257.48 93.06,257.48 87.35,251.77 87.03,251.77 84.17,248.91 v84.49,248.59
  Bottom 0.254: v269.28,258.75 274.99,258.75 275.94,257.8 277.85,257.8 286.1,249.54 287.37,249.54 A07.M1 | v266.1,286.05 264.51,287.64 244.19,287.64 v243.88,287.32 | v152.75,261.29 152.44,261.61 143.86,261.61 v142.91,260.66 | v142.91,262.88 142.28,262.24 138.47,262.24 v136.88,263.83 | v120.37,257.48 118.78,255.89 96.24,255.89 v94.65,257.48 | v84.49,248.59 84.17,248.27 83.54,248.27 81.63,246.37 76.24,246.37 75.28,247.32 A23.L2
06\  (via drill 0.61)
  Top 0.254: v78.46,235.26 79.09,235.89 79.09,239.7 v77.82,240.97 | v83.54,246.05 v79.41,241.92 | v99.73,257.48 101.32,259.07 101.32,264.15 103.54,266.37 103.54,267.96 110.21,274.62 120.69,274.62 v120.69,267.32 | v165.14,262.88 165.77,262.24 167.68,262.24 v167.68,260.02 | v214.03,256.85 215.94,258.75 215.94,261.29 216.25,261.61 216.25,266.05 216.89,266.69 v218.48,266.69 | v241.34,262.88 v241.34,260.66
  Route2 0.254: v99.73,257.48 v90.21,247.96 | v214.03,256.85 v211.49,254.3
  Route15 0.254: v130.21,265.1 133.39,265.1 137.51,269.23 v140.69,266.05 | v204.51,254.3 v198.79,260.02 | v223.87,261.29 v218.48,266.69 | v261.97,261.29 261.34,261.29 255.62,267 255.62,267.96 258.8,271.13 261.34,268.59 266.74,268.59 267.69,267.64 268.64,267.64 274.04,262.24 280.39,262.24 283.56,259.07 285.15,259.07 286.74,257.48 A07.H1
  Bottom 0.254: v78.46,235.26 75.28,235.26 A23.R2 | v77.82,240.97 78.78,241.92 v79.41,241.92 | v83.54,246.05 83.86,246.37 88.62,246.37 v90.21,247.96 | v120.69,267.32 124.18,267.32 124.81,267.96 127.35,267.96 v130.21,265.1 | v140.69,266.05 141.32,265.42 146.09,265.42 146.72,266.05 147.67,266.05 148.94,264.78 163.23,264.78 v165.14,262.88 | v167.68,260.02 168.63,259.07 195.93,259.07 197.2,260.34 198.47,260.34 v198.79,260.02 | v204.51,254.3 206.09,252.72 208.63,252.72 210.22,254.3 v211.49,254.3 | v223.87,261.29 224.19,261.61 235.3,261.61 235.94,260.97 238.48,260.97 239.11,261.61 240.38,261.61 v241.34,260.66 | v241.34,262.88 241.97,262.24 261.02,262.24 v261.97,261.29
07\  (via drill 0.61)
  Top 0.254: v69.25,232.08 69.57,232.4 69.57,236.84 v67.98,238.43 | v65.44,240.97 65.76,241.29 65.76,243.19 67.03,244.46 67.03,251.77 67.35,252.08 67.35,253.04 67.03,253.35 67.03,276.21 v81.63,290.82 | v174.66,292.72 174.34,292.41 174.34,224.46 173.71,223.83 v173.71,218.11 | v239.75,237.48 241.65,237.48 242.29,236.84 244.19,236.84 244.19,241.29 v243.88,241.61
  Route2 0.254: v65.44,240.97 v67.98,238.43 | v201.65,210.17 202.6,210.17 204.82,207.95 207.68,207.95 218.48,218.74 219.43,218.74 219.75,219.06 220.38,219.06 228,226.68 228.64,226.68 233.4,231.45 234.35,231.45 237.84,234.94 237.84,235.57 v239.75,237.48 | v265.78,251.13 274.67,242.24 275.63,242.24 v277.53,244.14
  Route15 0.254: v251.81,244.78 257.85,250.81 260.07,250.81 v261.66,252.4
  Bottom 0.254: v69.25,232.08 70.84,230.49 72.11,230.49 73.06,231.45 77.19,231.45 A23.S2 | v81.63,290.82 81.95,291.13 82.27,291.13 82.9,291.77 97.51,291.77 98.14,291.13 130.21,291.13 131.8,292.72 144.5,292.72 144.82,292.41 174.34,292.41 v174.66,292.72 | v173.71,218.11 178.47,213.35 178.47,211.12 180.69,211.12 181.33,210.49 184.5,210.49 185.14,209.86 201.33,209.86 v201.65,210.17 | v243.88,241.61 244.19,241.92 244.83,241.92 246.1,243.19 250.23,243.19 v251.81,244.78 | v261.66,252.4 261.97,252.08 264.83,252.08 v265.78,251.13 | v277.53,244.14 280.71,247.32 283.56,247.32 A07.L1
76  (via drill 0.61)
  Top 0.254: v306.11,96.83 307.38,95.55 307.38,93.02 308.01,92.38 v308.01,90.47
  Bottom 0.254: v306.11,96.83 295.63,96.83 294.36,98.1 C06.S2 | v308.01,90.47 308.33,90.16 314.36,90.16 315.31,89.21 C04.V2
76+77  (via drill 0.61)
  Top 0.254: v240.38,21.58 248.64,13.32 248.64,13.01 249.27,12.37 251.81,12.37 v251.81,13.64 | v340.08,72.38 340.71,73.01 340.71,80.95 v340.4,81.27
  Route2 0.254: v240.38,21.58 234.67,15.86 225.78,15.86 224.83,14.91 223.24,14.91 222.92,14.59 218.79,18.72 214.98,18.72 D12.V2 | v256.26,13.64 257.21,13.64 v266.1,4.75 | v341.03,111.75 341.03,112.07 342.62,113.65 342.62,124.77 344.52,126.67 344.52,128.26 337.54,135.24 338.17,135.88 C03.C1
  Route15 0.254: v347.38,60.63 347.38,61.9 340.08,69.2 v340.08,72.38 | v340.4,81.27 340.4,83.49 350.24,93.33 350.24,97.14 346.43,100.95 346.43,104.76 344.21,106.99 344.21,108.57 v341.03,111.75
  Bottom 0.254: v251.81,13.64 v256.26,13.64 | v266.1,4.75 266.42,5.07 280.07,5.07 280.39,4.75 287.69,4.75 288.96,6.02 360.4,6.02 373.42,19.04 373.42,58.41 350.87,58.41 348.65,60.63 v347.38,60.63
76\  (via drill 0.61)
  Top 0.254: 216.25,29.51 214.67,31.1 D12.R2 | 216.25,29.51 216.89,28.88 D12.S2 | v298.49,84.13 298.17,83.81 298.17,78.73 v299.12,77.77 | v304.52,72.69 305.15,72.06 305.15,67.3 304.84,66.98 v304.84,62.53 | v288.01,43.8 286.1,41.9 286.1,38.4 286.74,37.77 286.74,36.18 286.1,35.55 286.1,25.39 288.96,22.53 v288.96,4.75 | v273.4,4.12 266.74,4.12 263.88,1.26 213.4,1.26 213.4,18.09 213.08,18.4 213.08,26.34 216.25,29.51
  Route15 0.254: v298.49,84.13 291.82,90.79 291.82,92.7 290.87,93.65 290.87,94.6 C06.T2 | v299.12,77.77 299.44,77.77 v304.52,72.69
  Bottom 0.254: v304.84,62.53 299.44,57.14 299.44,55.23 v288.01,43.8 | v288.96,4.75 288.33,4.12 v273.4,4.12
77
  Bottom 0.254: C06.U2 294.36,91.74 295.95,90.16 299.12,90.16 300.07,89.21 302.61,89.21 C05.V2
77\  (via drill 0.61)
  Top 0.254: D12.T2 214.67,24.75 216.89,22.53 D12.U2 | v295.31,77.14 v295.31,84.13 | v299.76,58.72 299.44,58.41 299.44,55.23 298.8,54.6 298.8,50.79 301.66,47.93 301.66,47.29 301.03,46.66 301.03,42.21 301.34,41.9 301.34,40.63 301.03,40.31 v301.03,39.04 | v267.69,16.18 267.37,16.5 v267.37,20.31 | v254.99,18.09 254.35,17.45 254.35,11.42 254.04,11.1 236.89,11.1 v236.89,14.59 | v226.1,14.91 225.78,15.23 v225.78,24.12
  Route15 0.254: v292.77,87.94 293.72,86.98 293.72,85.71 v295.31,84.13 | v295.31,77.14 295.31,67.3 298.17,64.44 298.17,62.53 298.49,62.22 298.49,60 v299.76,58.72 | v225.78,24.12 222.92,24.12 v221.65,22.85
  Bottom 0.254: v292.77,87.94 292.45,88.25 291.5,88.25 291.18,88.57 C06.V2 | v301.03,39.04 294.99,33.01 291.18,33.01 290.87,33.32 290.23,33.32 288.33,31.42 288.33,29.51 288.64,29.2 288.64,26.34 282.29,19.99 282.29,17.13 273.72,17.13 272.77,16.18 v267.69,16.18 | v267.37,20.31 264.2,20.31 263.56,19.67 261.34,19.67 259.43,17.77 255.31,17.77 v254.99,18.09 | v236.89,14.59 236.26,15.23 226.41,15.23 v226.1,14.91 | v221.65,22.85 221.33,22.53 218.16,22.53 D12.U2
+3V@A09U1  (via drill 0.61)
  Top 0.254: A08.F2 265.15,256.21 267.69,253.67 267.69,251.77 268.01,251.45 A08.K2 268.01,250.18 266.42,248.59 266.42,229.22 266.74,228.9 v266.74,227.32 | B13.U2 204.51,156.2 203.55,157.15 v203.55,165.09 203.55,169.21 206.09,171.76 v206.09,184.46 | A07.T2 v277.85,225.73 | v207.68,185.73 209.27,187.31 209.27,213.03 209.59,213.35 v209.59,221.6
  Bottom 0.254: A08.D1 271.18,266.05 271.18,262.56 269.28,262.56 267.37,260.66 265.78,260.66 A08.F2 | v203.55,165.09 B13.R1 | 266.74,227 275.94,227 277.21,225.73 v277.85,225.73 | 266.74,227 263.88,227 262.61,225.73 A09.U1 258.8,225.41 256.89,223.51 251.81,223.51 249.27,220.97 213.71,220.97 212.76,221.92 209.9,221.92 v209.59,221.6 | A07.T2 278.48,228.9 280.71,231.13 A07.S2 281.66,231.45 286.74,231.45 A07.S1 | v206.09,184.46 207.36,185.73 v207.68,185.73 | 266.74,227 v266.74,227.32
+3V@B12U1  (via drill 0.61)
  Top 0.254: B14.A1 198.16,205.73 197.2,204.77 197.2,197.79 199.11,195.89 199.11,194.93 201.65,192.39 B13.F2 201.97,189.85 203.24,188.58 v203.24,184.46 | 190.22,164.77 190.22,169.85 189.27,170.8 B14.N2 188.95,174.61 191.49,177.15 191.49,180.01 191.81,180.33 B14.K2 | 190.22,164.77 190.22,157.79 191.81,156.2 B14.U2 | 190.22,164.77 v191.17,164.77
  Bottom 0.254: B13.F2 201.97,191.12 201.97,194.93 202.92,194.93 204.51,196.52 207.36,196.52 B13.D1 | v191.17,164.77 194.66,164.77 B14.R1 | B12.U1 223.24,155.88 219.11,155.88 218.16,156.83 215.94,156.83 215.3,156.2 212.44,156.2 211.49,157.15 203.55,157.15 202.6,156.2 199.74,156.2 199.11,156.83 196.25,156.83 194.98,155.56 B14.U2 | 203.24,182.23 193.71,182.23 192.76,181.28 B14.K2 | 203.24,182.23 205.46,182.23 206.73,180.96 B13.K1 | 203.24,182.23 v203.24,184.46
+3V@C08U1  (via drill 0.61)
  Top 0.254: C05.N2 302.93,108.57 302.93,113.65 C05.L2 | C04.N2 315.63,108.57 315.63,113.65 C04.L2 | v325.79,138.1 324.2,138.1 324.2,132.07 324.52,131.75 324.52,131.11 323.57,130.16 323.57,122.22 322.62,121.27 C04.J1 | v305.47,107.3 305.15,106.99 305.15,93.65 306.11,92.7 C05.U2
  Bottom 0.254: C08.U1 275.31,92.38 275.63,92.7 279.75,92.7 280.39,93.33 301.66,93.33 302.61,92.38 305.79,92.38 C05.U2 307.06,92.38 311.19,92.38 312.14,93.33 313.41,93.33 314.68,92.06 C04.U2 | C01.C1 360.08,136.51 358.49,138.1 356.91,138.1 355.64,136.83 351.51,136.83 C02.C1 350.24,136.83 349.92,137.15 345.79,137.15 344.84,138.1 v325.79,138.1 | 314.36,118.73 315.63,117.46 315.63,114.92 C04.L2 | 314.36,118.73 313.41,119.69 310.87,119.69 310.23,120.32 C05.J1 | 314.36,118.73 320.08,118.73 321.66,120.32 C04.J1 | C04.N2 312.77,107.94 311.5,109.21 304.84,109.21 303.88,108.25 C05.N2 303.88,107.62 305.15,107.62 v305.47,107.3
+3V@C15U1  (via drill 0.61)
  Top 0.254: 196.57,134.93 195.62,133.97 C14.D1 | 196.57,134.93 196.57,138.42 198.16,140.01 198.16,142.23 C14.A1 | 196.57,134.93 196.57,123.81 197.84,122.54 197.84,118.41 198.16,118.1 C14.K1 | 187.04,117.78 187.04,121.91 188.63,123.49 188.63,126.35 C14.F2 | 187.04,117.78 187.04,93.65 186.09,92.7 C15.U1 | 187.04,117.78 v188,117.78
  Bottom 0.254: C14.K1 197.84,117.14 192.76,117.14 C14.K2 191.49,117.78 v188,117.78 | C16.H2 167.36,124.13 168.31,125.08 180.06,125.08 180.69,125.72 187.36,125.72 188.31,126.67 C14.F2
+3V@D09U1  (via drill 0.61)
  Top 0.254: v278.48,22.53 278.17,22.85 278.17,24.75 D07.T2
  Bottom 0.254: v278.48,22.53 277.21,22.53 275.94,23.8 268.01,23.8 267.05,22.85 262.93,22.85 262.61,22.53 D09.U1 | D07.T2 278.48,25.71 280.71,27.93 D07.S2 281.66,28.25 286.74,28.25 D07.S1
+3V@D10U1
  Top 0.254: D11.F2 227.37,56.5 227.68,56.18 227.68,52.06 229.91,49.83 229.91,48.25 D11.K2 | D10.N2 239.43,38.72 239.43,43.8 D10.L2 | D10.U1 248.64,21.89 244.19,21.89 244.19,39.68 243.24,40.63 D10.M2
  Bottom 0.254: D11.K2 D11.K1 236.89,46.98 239.11,44.75 D10.L2 | D11.D1 233.08,62.85 233.08,59.68 232.45,59.68 230.22,57.46 227.68,57.46 D11.F2 | D14.M1 199.11,41.58 200.06,42.53 237.53,42.53 239.11,44.12 D10.L2 | D10.M2 242.29,41.58 240.07,43.8 D10.L2
-15V  (via drill 0.61)
  Top 0.635: v189.9,144.77 189.9,142.86 190.85,141.91 190.85,137.46 190.54,137.15 190.54,88.25 189.9,87.62 189.9,71.11 189.27,70.47 D14.B2 | v140.05,146.04 140.37,146.36 140.37,154.29 139.74,154.93 139.74,166.68 139.1,167.31 139.1,170.17 139.74,170.8 139.74,185.73 139.1,186.36 139.1,189.22 139.74,189.85 139.74,198.11 138.47,199.38 138.47,202.55 B18.B2 | 355.79,261.77 356.91,262.88 AB01.AE2 | 355.79,261.77 354.68,260.66 AB01.AF2 | AB01.AB2 354.37,272.4 355.64,271.13 355.64,261.93 355.79,261.77 | A18.B2 v138.15,279.39 | B20.B2 113.07,203.82 114.02,204.77 114.02,221.29 114.34,221.6 114.34,229.86 113.7,230.49 113.7,233.67 114.34,234.3 114.34,267.96 112.75,269.55 A20.B2
  Bottom 0.635: 85.6,201.76 86.71,202.87 B22.B2 | 85.6,201.76 85.44,201.6 76.55,201.6 75.28,202.87 B23.B2 | 85.6,201.76 85.76,201.6 98.14,201.6 99.41,202.87 B21.B2 100.68,202.87 102.27,202.87 103.54,201.6 107.03,201.6 108.62,203.19 B20.B2 113.38,202.87 114.65,201.6 132.43,201.6 134.02,203.19 B18.B2 | v189.9,144.77 188.63,146.04 v140.05,146.04 | A23.B2 75.28,272.72 76.55,271.45 85.44,271.45 86.71,272.72 A22.B2 87.98,272.72 91.79,272.72 93.06,271.45 94.33,271.45 95.29,272.4 99.1,272.4 99.41,272.72 A21.B2 103.22,273.04 104.81,271.45 107.03,271.45 108.3,272.72 112.11,272.72 A20.B2 113.38,272.72 114.34,272.72 115.61,271.45 132.43,271.45 134.02,273.04 A18.B2 | v138.15,279.39 275.31,279.39 276.58,278.12 344.84,278.12 348.33,274.62 352.14,274.62 353.41,273.36 AB01.AB2
ADDR_ACC  (via drill 0.61)
  Top 0.254: v156.25,98.73 155.93,99.05 155.93,106.35 156.88,107.3 C17.N1 | v163.23,91.74 167.68,87.3 171.49,87.3 v171.49,87.94 | v181.96,79.68 181.65,79.36 181.65,70.79 181.01,70.16 181.01,46.66 180.69,46.34 180.69,33.01 v180.38,32.69 | v184.19,32.37 185.14,31.42 185.14,30.78 183.23,28.88 183.23,28.25 184.19,27.29 187.36,27.29 v187.36,27.61 | v212.76,37.14 213.4,37.14 213.71,36.82 218.48,36.82 218.48,40.31 219.43,41.26 v219.43,41.58 | v229.27,31.74 228.95,31.42 228.95,27.93 231.18,25.71 231.18,23.16 231.49,22.85 231.49,19.35 230.54,18.4 230.54,9.51 231.18,8.88 258.48,8.88 v258.48,9.83 | v281.34,18.09 281.66,17.77 v281.66,9.51 | v310.23,9.83 317.54,17.13 317.54,22.53 320.71,25.71 320.71,32.06 321.03,32.37 321.03,37.45 320.71,37.77 320.71,38.4 321.66,39.36 v321.66,40.63 | v323.25,41.58 323.57,41.9 323.57,52.69 v323.25,53.01
  Route2 0.254: v202.92,28.88 203.24,28.88 210.54,36.18 211.81,36.18 v212.76,37.14 | v323.25,53.01 323.25,56.18 326.74,59.68 326.74,64.44 332.14,69.84 332.14,71.43 333.09,72.38 333.09,75.87 340.71,83.49 340.71,87.94 341.03,88.25 C02.V2
  Route15 0.254: v163.23,91.74 v156.25,98.73 | v171.49,87.94 171.49,86.66 v173.39,84.76 | v219.43,41.58 v229.27,31.74 | v258.48,9.83 266.74,9.83 v274.99,18.09
  Bottom 0.254: v173.39,84.76 178.47,79.68 v181.96,79.68 | v180.38,32.69 180.69,33.01 183.55,33.01 v184.19,32.37 | v187.36,27.61 187.68,27.29 192.76,27.29 193.08,27.61 197.52,27.61 197.84,27.29 201.33,27.29 v202.92,28.88 | v274.99,18.09 275.31,17.77 281.02,17.77 v281.34,18.09 | v281.66,9.51 281.98,9.83 v310.23,9.83 | v321.66,40.63 322.62,41.58 v323.25,41.58
ADDR_ACC\  (via drill 0.61)
  Top 0.254: v258.16,162.23 v261.02,159.37
  Route2 0.254: v163.87,105.08 171.17,112.38 172.44,112.38 178.79,118.73 182.6,118.73 193.39,129.53 195.93,129.53 197.84,131.43 201.65,131.43 234.67,164.45 234.67,165.09 235.62,166.04 236.89,166.04 v241.97,171.12
  Route15 0.254: v246.42,173.02 254.04,165.4 254.04,165.09 254.67,164.45 255.94,164.45 v258.16,162.23
  Bottom 0.254: v163.87,105.08 161.01,105.08 C17.P1 | v241.97,171.12 242.92,172.07 244.83,172.07 245.78,173.02 v246.42,173.02 | v261.02,159.37 261.34,159.05 264.51,159.05 B08.T2
B-BRK  (via drill 0.61)
  Top 0.254: B10.T2 239.43,159.37 239.43,164.45 B10.R2 | v225.14,153.66 225.14,87.94 225.46,87.62 225.46,76.5 225.14,76.19 225.14,46.98 224.51,46.34 224.51,42.21 224.19,41.9 D12.M1 | v365.16,145.72 365.16,132.07 363.89,130.8 C01.E1 | v242.92,146.04 B10.U2 242.61,156.2 242.61,161.28 B10.S2
  Bottom 0.254: B10.S2 242.29,162.23 240.07,164.45 B10.R2 | v225.14,153.66 237.84,153.66 238.48,154.29 241.34,154.29 242.29,155.24 B10.U2 | v365.16,145.72 243.24,145.72 v242.92,146.04
B-BRK\  (via drill 0.61)
  Top 0.254: v350.56,195.89 350.56,199.38 B02.C1 | v332.46,153.98 v332.46,146.67
  Bottom 0.254: 347.06,168.58 346.11,169.53 344.84,169.53 344.84,173.98 B02.M2 344.84,175.25 344.84,179.69 345.16,179.69 346.11,180.64 346.11,183.82 347.06,183.82 B02.J1 347.38,184.77 347.38,189.22 343.57,189.22 | 347.06,168.58 350.24,168.58 B02.P1 | 343.57,189.22 342.94,189.22 341.98,190.17 B02.F2 | v350.56,195.89 347.7,193.03 347.38,193.03 343.57,189.22 | v332.46,146.67 332.14,146.36 245.46,146.36 241.97,149.85 240.07,149.85 240.07,151.75 B10.V2 | v332.46,153.98 335,156.52 336.59,156.52 338.81,158.74 | 338.81,158.74 B02.T2 | 347.06,168.58 347.06,166.99 346.11,166.99 345.79,166.68 345.79,164.45 344.52,164.45 338.81,158.74
B-RUN  (via drill 0.61)
  Top 0.254: v226.73,174.3 226.73,172.07 B11.N2 | v222.6,203.51 224.51,203.51 224.51,205.09 225.46,206.05 v225.46,207 | v274.04,223.83 275.31,222.55 v275.31,218.11 | v306.11,219.7 308.33,221.92 308.33,223.19 308.96,223.83 v308.96,224.46 | v352.46,216.21 352.14,215.89 352.14,207.95 352.78,207.31 352.78,199.38 v353.41,198.74
  Route2 0.254: v245.78,213.98 248.32,213.98 250.23,215.89 250.23,217.48 252.13,219.38 252.45,219.38 253.08,220.02 253.08,220.65 254.67,222.24 255.62,222.24 261.34,227.95 262.29,227.95 v264.2,226.05 | v316.58,224.46 318.17,224.46 323.25,219.38 324.2,220.33 325.47,220.33 v327.7,218.11 | v363.89,176.2 371.51,168.58 371.51,154.61 370.24,153.34 370.24,152.39 362.94,145.08 362.94,144.13 362.3,143.5 362.3,141.91 360.72,140.32 C01.B1
  Route15 0.254: v226.73,174.3 223.24,177.79 223.24,179.69 219.43,183.5 219.43,187.95 218.16,189.22 218.16,192.39 223.87,198.11 222.6,199.38 v222.6,203.51 | v225.46,207 225.46,210.49 v228.95,213.98 | v330.24,215.57 337.22,215.57 v337.86,214.93 | v353.41,198.74 351.19,196.52 351.51,196.2 351.51,194.93 352.14,194.3 352.14,187.95 v363.89,176.2
  Bottom 0.254: v228.95,213.98 230.86,215.89 245.15,215.89 245.46,216.21 246.1,216.21 246.73,215.57 246.73,213.98 v245.78,213.98 | v264.2,226.05 266.42,223.83 v274.04,223.83 | v275.31,218.11 276.58,216.84 301.03,216.84 301.98,217.79 303.25,217.79 304.2,218.74 305.15,218.74 v306.11,219.7 | v308.96,224.46 309.28,224.14 316.27,224.14 v316.58,224.46 | v327.7,218.11 v330.24,215.57 | v337.86,214.93 338.49,215.57 351.83,215.57 v352.46,216.21
B-XSTA  (via drill 0.61)
  Top 0.254: v224.51,76.82 222.6,74.92 222.6,61.9 223.56,60.95 D12.E1 | v247.69,81.9 247.37,82.22 v247.37,90.16 | v253.72,90.16 253.72,102.22 v252.77,103.18 | v240.07,103.81 239.43,104.44 v239.43,105.72 | v201.97,249.54 200.38,249.54 200.38,222.87 v200.06,222.55 | v191.81,221.29 191.81,215.89 v192.76,214.93 | v194.35,188.27 194.03,187.95 194.03,174.61 v194.35,174.3
  Route2 0.254: v192.76,214.93 192.76,213.98 191.81,213.03 191.81,209.22 191.17,208.58 191.17,207.31 190.54,206.68 190.54,197.15 195.3,192.39 194.03,191.12 194.03,188.58 v194.35,188.27
  Route15 0.254: v224.19,254.3 227.37,251.13 240.07,263.83 242.29,263.83 A10.E2 | v194.35,174.3 192.44,172.39 193.39,171.44 193.39,170.49 198.16,165.72 198.16,164.14 202.92,159.37 202.92,154.29 204.19,153.02 204.19,147.31 205.46,146.04 205.46,144.13 209.27,140.32 209.27,135.24 214.98,129.53 214.98,128.26 215.62,127.62 215.62,123.81 216.89,122.54 216.89,120 228.32,108.57 228.32,106.99 229.91,105.4 C11.P2
  Bottom 0.254: v224.51,76.82 224.83,76.5 246.1,76.5 248,78.41 248,81.9 v247.69,81.9 | v247.37,90.16 v253.72,90.16 | v252.77,103.18 252.45,102.86 241.02,102.86 v240.07,103.81 | v239.43,105.72 239.11,106.03 235.62,106.03 234.99,105.4 230.54,105.4 C11.P2 | v224.19,254.3 221.97,252.08 209.9,252.08 208.95,251.13 207.05,251.13 205.46,249.54 v201.97,249.54 | v200.06,222.55 198.47,220.97 192.12,220.97 v191.81,221.29
BAC_00  (via drill 0.61)
  Top 0.254: v287.06,197.15 287.06,199.38 B07.C1
  Bottom 0.254: v287.06,197.15 284.83,197.15 B07.D1 | B06.B1 296.26,202.87 294.99,201.6 289.28,201.6 288.01,200.33 B07.C1
BAC_00\  (via drill 0.61)
  Top 0.254: v237.84,12.05 237.84,26.34 241.02,29.51 241.02,44.12 241.65,44.75 241.65,49.2 245.78,53.33 245.78,56.5 D10.F1 | v113.38,12.37 111.48,14.27 111.48,161.91 114.02,164.45 114.02,200.65 122.91,209.54 v122.91,210.17 | v144.18,214.93 145.77,216.52 v145.77,252.08 | v259.12,255.58 260.07,256.53 260.07,266.05 v260.39,266.37 | v280.71,267.96 279.75,267 279.75,255.58 | 279.75,255.58 279.75,241.61 279.12,240.97 279.12,236.84 v278.8,236.52 | v294.36,223.19 294.68,222.87 294.68,207.31 295.31,206.68 v295.31,205.41 | v338.49,140.01 338.49,141.27 339.44,142.23 339.44,153.34 v339.13,153.66 | v359.76,160.64 359.13,161.28 359.13,167.63 v359.76,168.26 | v342.62,207.63 341.98,208.27 341.98,217.79 v342.94,218.74 | v353.73,218.74 355.32,220.33 355.32,246.37 v355.64,246.68 | v281.34,255.58 279.75,255.58
  Route15 0.254: v341.67,156.2 v339.13,153.66 | v348.02,200.96 342.94,206.05 342.94,207.31 v342.62,207.63
  Bottom 0.254: v237.84,12.05 221.02,12.05 220.38,11.42 115.61,11.42 114.65,12.37 v113.38,12.37 | v122.91,210.17 127.67,214.93 v144.18,214.93 | v145.77,252.08 186.41,252.08 188.95,249.54 199.11,249.54 199.74,250.18 199.74,254.62 199.11,255.26 199.11,255.89 199.74,256.53 203.55,256.53 204.19,255.89 251.81,255.89 252.45,255.26 258.8,255.26 v259.12,255.58 | v260.39,266.37 261.34,267.32 263.88,267.32 264.51,267.96 273.09,267.96 273.72,267.32 276.58,267.32 277.21,267.96 v280.71,267.96 | v278.8,236.52 279.12,236.21 285.15,236.21 291.18,230.18 297.22,230.18 298.49,228.9 298.49,226.68 297.85,226.68 v294.36,223.19 | v295.31,205.41 296.9,207 299.76,207 B06.A1 | v338.49,140.01 335.63,140.01 C03.B1 | v341.67,156.2 342.62,157.15 354.37,157.15 356.91,159.69 358.81,159.69 v359.76,160.64 | v359.76,168.26 359.76,170.17 358.81,171.12 358.81,182.23 358.49,182.55 358.49,186.68 359.13,187.31 359.13,191.12 357.86,191.12 355.95,193.03 355.95,198.43 355,198.43 352.14,201.28 348.33,201.28 v348.02,200.96 | v342.94,218.74 343.25,219.06 353.41,219.06 v353.73,218.74 | v355.64,246.68 355.64,249.23 349.92,249.23 346.75,252.4 339.76,252.4 336.9,255.26 329.28,255.26 328.97,255.58 306.74,255.58 306.42,255.89 281.66,255.89 v281.34,255.58
BAC_01
  Bottom 0.254: B07.F2 278.48,190.8 280.71,193.03 B07.E2 281.66,193.98 284.2,193.98 285.15,194.93 298.49,194.93 299.44,193.98 B06.E1
BAC_01\  (via drill 0.61)
  Top 0.254: v127.67,14.27 126.72,15.23 126.72,64.76 124.18,67.3 124.18,75.87 124.5,76.19 v124.5,85.71 | v114.97,86.66 114.65,86.98 114.65,146.67 114.97,146.99 114.97,154.61 114.65,154.93 114.65,156.2 v115.61,157.15 | v159.42,159.05 159.1,159.37 159.1,164.14 159.74,164.77 159.74,166.99 159.1,167.63 159.1,207 159.42,207.31 159.42,224.46 159.1,224.78 159.1,226.05 159.42,226.36 159.42,230.81 158.47,231.76 158.47,263.51 v161.33,266.37 | v228,268.28 228.64,268.91 228.64,276.53 231.18,279.07 231.18,296.53 231.81,297.17 240.07,297.17 240.07,286.05 v240.7,285.42 | v303.25,283.2 304.84,281.61 304.84,254.94 308.01,251.77 v308.01,230.18 | v300.71,229.86 299.76,228.9 v299.76,227.32 | v297.85,225.09 298.17,224.78 298.17,211.76 v299.12,210.81 | v302.61,206.36 v302.61,210.17 | v300.71,204.46 299.76,203.51 v299.76,202.24 | v297.22,199.7 297.22,197.47 B06.D1 | D10.H1 248.96,53.33 248,52.38 248,31.74 250.54,29.2 250.54,18.72 v249.27,17.45 249.59,17.13 v249.59,13.32 | v337.86,127.3 337.86,129.53 C03.E1 | v311.5,84.76 v311.5,87.94 | v310.23,77.46 310.23,75.55 309.6,74.92 v309.6,73.97 | v297.53,68.25 297.85,67.93 297.85,64.44 298.17,64.12 298.17,62.53 v297.53,61.9 | v294.36,58.72 294.68,58.41 294.68,54.92 295.63,53.96 295.63,48.57 298.17,46.03 298.17,38.72 298.49,38.4 298.49,23.48 294.04,19.04 v294.04,13.96
  Route2 0.254: v354.37,115.88 356.59,113.65 347.38,104.44 347.38,103.18 v338.17,93.97
  Route15 0.254: v337.86,127.3 341.35,123.81 v341.67,123.81 | v349.92,120.96 v348.02,122.86
  Bottom 0.254: v249.27,17.45 248.96,17.13 223.24,17.13 222.92,17.45 221.97,17.45 218.48,13.96 127.99,13.96 v127.67,14.27 | v124.5,85.71 123.54,86.66 v114.97,86.66 | v115.61,157.15 115.92,156.83 157.2,156.83 v159.42,159.05 | v161.33,266.37 162.91,267.96 171.49,267.96 172.12,267.32 174.98,267.32 175.61,267.96 184.19,267.96 184.82,267.32 187.68,267.32 188.31,267.96 222.29,267.96 222.92,267.32 225.78,267.32 226.73,268.28 v228,268.28 | v240.7,285.42 240.7,284.15 241.02,284.15 241.65,283.51 269.59,283.51 270.55,284.47 300.07,284.47 301.66,282.88 302.93,282.88 v303.25,283.2 | v308.01,230.18 307.69,229.86 v300.71,229.86 | v299.76,227.32 299.12,226.68 299.12,226.36 v297.85,225.09 | v299.12,210.81 299.76,210.17 v302.61,210.17 | v302.61,206.36 v300.71,204.46 | v299.76,202.24 v297.22,199.7 | v341.67,123.81 341.98,123.49 342.94,123.49 343.89,122.54 347.7,122.54 v348.02,122.86 | v349.92,120.96 352.46,118.41 352.46,115.88 v354.37,115.88 | v338.17,93.97 339.44,92.7 339.44,90.79 327.38,90.79 324.2,87.62 311.82,87.62 v311.5,87.94 | v311.5,84.76 311.5,78.41 311.19,78.41 v310.23,77.46 | v309.6,73.97 309.28,74.28 303.57,74.28 v297.53,68.25 | v294.36,58.72 v297.53,61.9 | v294.04,13.96 293.72,13.64 292.14,13.64 291.5,13.01 271.82,13.01 271.5,12.69 250.23,12.69 v249.59,13.32
BAC_02  (via drill 0.61)
  Top 0.254: v284.52,180.33 284.52,183.5 B07.J1
  Bottom 0.254: B07.J1 284.83,184.46 285.79,185.41 294.99,185.41 296.58,186.99 299.44,186.99 B06.H1 | v284.52,180.33 286.42,180.33 286.74,180.64 B07.K1
BAC_02\  (via drill 0.61)
  Top 0.254: v247.37,30.15 247.37,49.2 246.42,50.15 D10.J1 | v284.2,23.16 286.74,20.62 v286.74,16.18 | v359.76,16.5 362.3,19.04 362.3,50.79 v362.62,51.1 | v363.57,81.9 v363.57,78.41 | v361.03,84.44 358.49,86.98 358.49,100 357.54,100.95 v357.54,103.18 | v348.33,104.13 347.7,104.76 v347.7,106.03 | v337.86,112.7 339.44,114.29 339.44,121.27 338.49,122.22 338.49,123.18 C03.H1
  Route2 0.254: 338.49,107.94 338.49,108.57 336.59,110.48 336.9,110.8 336.9,111.75 v337.86,112.7 | 338.49,107.94 v338.49,106.99 | v299.76,190.8 299.76,189.54 303.25,186.04 301.98,184.77 301.98,183.5 308.96,176.52 318.49,176.52 319.12,177.15 320.39,177.15 326.43,171.12 331.19,175.88 334.05,175.88 334.68,176.52 336.9,176.52 341.67,181.28 342.3,181.28 344.52,183.5 346.11,183.5 348.02,181.6 350.24,183.82 350.87,183.82 357.22,177.47 356.91,177.15 356.91,176.52 357.54,175.88 359.13,175.88 370.88,164.14 370.88,159.05 369.61,157.79 369.61,154.29 362.94,147.62 362.94,146.99 359.76,143.81 359.76,142.55 357.86,140.64 357.86,139.05 355.64,136.83 355.64,130.48 352.46,127.3 352.46,126.99 350.87,125.4 349.29,125.4 347.06,123.18 347.06,121.91 343.25,118.1 343.25,112.7 338.49,107.94
  Route15 0.254: v280.71,26.66 v278.17,29.2 | v354.37,59.36 v362.62,51.1
  Bottom 0.254: v247.37,30.15 247.69,29.83 258.8,29.83 261.34,27.29 263.88,27.29 265.78,29.2 267.05,29.2 267.69,29.83 277.53,29.83 v278.17,29.2 | v280.71,26.66 281.02,26.98 284.52,26.98 285.79,25.71 285.79,24.44 285.47,24.44 v284.2,23.16 | v286.74,16.18 287.06,16.5 v359.76,16.5 | v354.37,59.36 354.68,59.04 364.53,59.04 369.61,64.12 369.61,78.41 v363.57,78.41 | v361.03,84.44 v363.57,81.9 | v357.54,103.18 357.22,103.49 355.95,103.49 355.64,103.81 351.83,103.81 351.51,103.49 348.97,103.49 v348.33,104.13 | v347.7,106.03 347.38,106.35 339.13,106.35 v338.49,106.99 | v299.76,190.8 297.53,190.8 B06.F1
BAC_03
  Top 0.254: B07.N2 278.48,171.76 280.71,173.98 B07.M2
  Bottom 0.254: B06.K1 299.44,180.64 299.12,180.33 296.26,180.33 291.82,175.88 284.2,175.88 282.93,174.61 B07.M2
BAC_03\  (via drill 0.61)
  Top 0.254: v243.88,46.03 241.65,43.8 241.65,29.2 238.48,26.02 238.48,15.23 v238.8,14.91 | v340.08,14.59 358.81,14.59 358.81,39.68 359.76,40.63 359.76,43.17 359.13,43.8 359.13,67.3 359.45,67.61 359.45,68.57 355.32,72.69 v355.32,73.33 | v349.29,79.36 348.97,79.68 348.97,90.47 347.7,91.74 v347.7,93.33 | v315.63,166.99 316.58,167.95 v316.58,168.58 | v337.54,146.99 v337.54,152.39 | v335.63,142.23 v335.63,146.67 | v350.24,140.96 349.92,140.64 349.92,137.46 349.6,137.15 349.6,129.21 v350.24,128.58
  Route2 0.254: v355.32,73.33 v349.29,79.36 | v343.57,126.99 339.13,122.54 339.13,118.73 338.49,118.1 C03.K1
  Route15 0.254: v347.7,93.33 346.11,94.92 346.11,100.32 345.79,100.63 345.79,101.59 343.25,104.13 343.25,108.25 340.08,111.43 340.08,115.24 338.49,116.83 C03.K1 | v300.71,184.14 307.06,177.79 307.06,175.88 310.87,172.07 310.87,171.12 v311.19,170.8 | v337.54,152.39 v322.62,167.31
  Bottom 0.254: v243.88,46.03 244.19,46.34 247.69,46.34 248.64,47.29 D10.K1 | v238.8,14.91 239.11,15.23 255.94,15.23 257.85,13.32 271.18,13.32 271.5,13.64 291.18,13.64 292.45,14.91 339.76,14.91 v340.08,14.59 | v311.19,170.8 312.14,169.85 313.09,169.85 315.63,167.31 v315.63,166.99 | v316.58,168.58 318.17,166.99 319.76,166.99 320.08,167.31 v322.62,167.31 | v337.54,146.99 337.22,146.67 v335.63,146.67 | v335.63,142.23 336.27,141.59 338.81,141.59 339.13,141.91 343.57,141.91 344.52,140.96 v350.24,140.96 | v350.24,128.58 349.92,128.26 344.84,128.26 v343.57,126.99 | v300.71,184.14 B06.J1
BAC_04  (via drill 0.61)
